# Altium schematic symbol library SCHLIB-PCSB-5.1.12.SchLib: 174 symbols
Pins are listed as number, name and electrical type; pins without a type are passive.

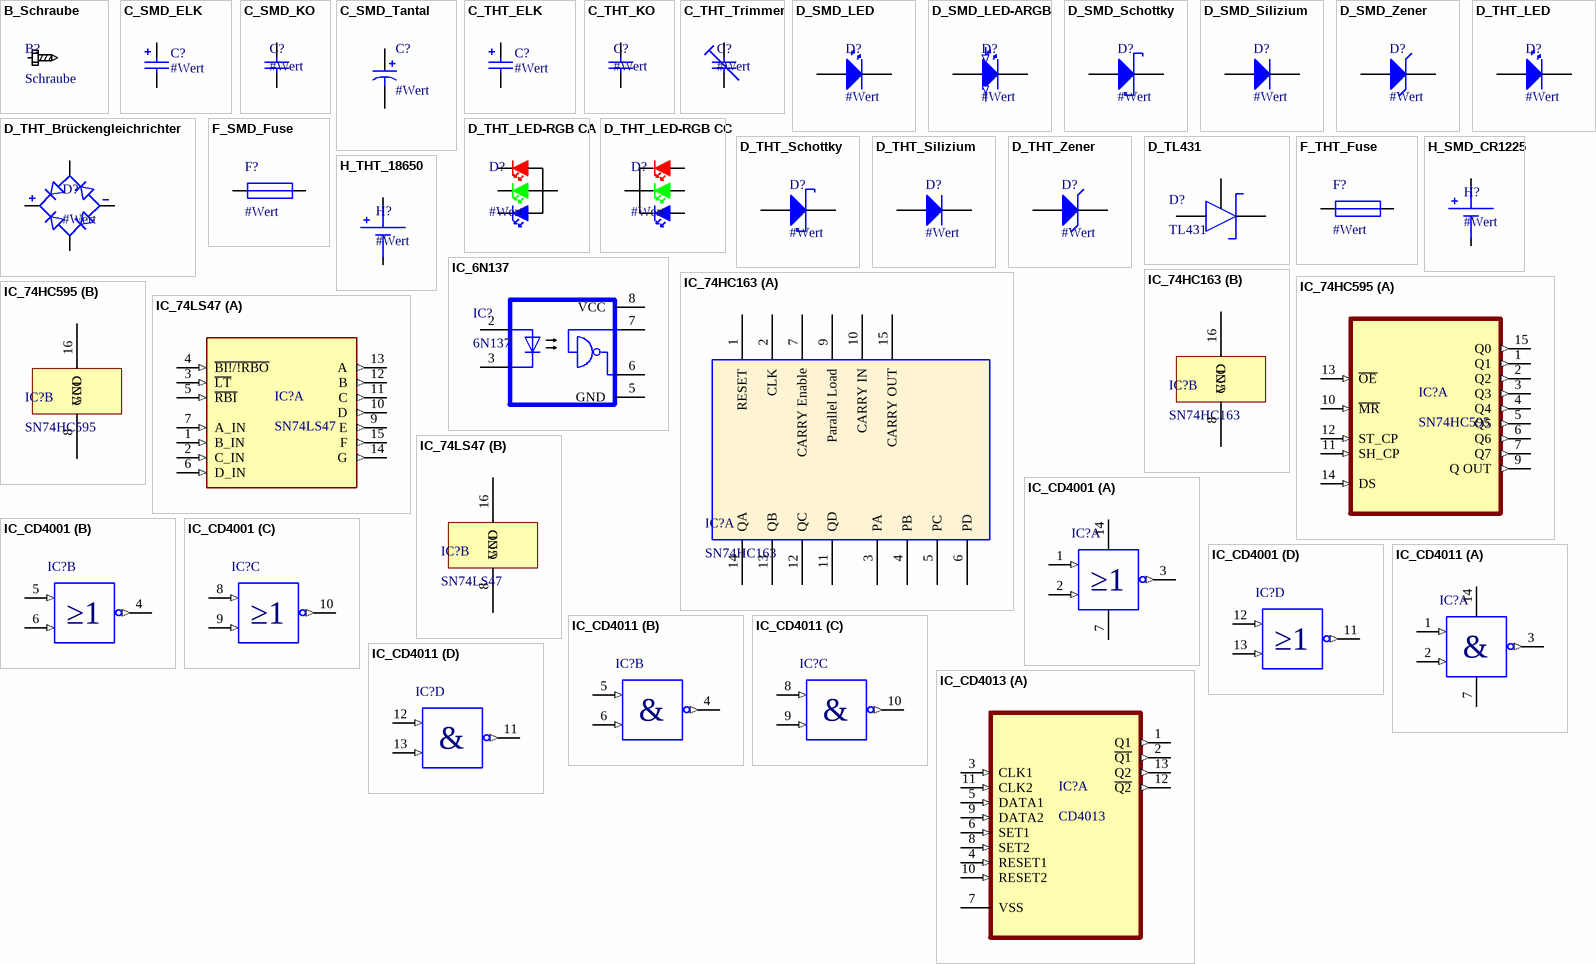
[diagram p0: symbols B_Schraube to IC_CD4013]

## B_Schraube
designator B?, comment Schraube
Schraubenloch für M3 Schrauben
footprint B_Schraube-M3 PAD (LB-2024-04-18)
footprint B_Schraube-M3 (LB-2024-04-18)
pins: 1 PAD

## C_SMD_ELK
designator C?, comment #Wert
SMD Elektrolytkondensator
footprint C_SMD_B-Typ (LB-2024-04-16)
footprint C_SMD_C-TYP (LB-2024-04-15)
footprint C_SMD_D-TYP (LB-2024-04-16)
footprint C_SMD_D8-TYP (LB-2024-04-16)
footprint C_SMD_F-TYP (LB-2024-04-16)
footprint C_SMD_G-TYP (LB-2024-04-16)
pins: 1, 2

## C_SMD_KO
designator C?, comment #Wert
Kondensator SMD Universal, Keramik, Folie, usw.
footprint C_SMD_0603 (LB-2024-04-17)
footprint C_SMD_0805 (LB-2024-04-17)
footprint C_SMD_1206 (LB-2024-04-17)
footprint C_SMD_1808C (LB-2024-04-17)
footprint C_SMD_2010R (LB-2024-04-17)
pins: 1, 2

## C_SMD_Tantal
designator C?, comment #Wert
Tantalkondensator
footprint C_SMD_Tan_1206 (LB-2024-04-25)
footprint C_SMD_B-Typ (LB-2024-04-16)
footprint C_SMD_C-TYP (LB-2024-04-15)
footprint C_SMD_D-TYP (LB-2024-04-16)
footprint C_SMD_D8-TYP (LB-2024-04-16)
footprint C_SMD_F-TYP (LB-2024-04-16)
footprint C_SMD_G-TYP (LB-2024-04-16)
pins: 1, 2

## C_THT_ELK
designator C?, comment #Wert
THT Elektrolytkondensator
footprint C_THT_RB-.3/.6 (LB-2024-04-15)
footprint C_THT_RB-.2/.4 (LB-2024-04-16)
footprint C_THT_RB-.1/.3 (LB-2024-04-15)
footprint C_THT_RB-.1/.2 (LB-2024-04-15)
pins: 1, 2

## C_THT_KO
designator C?, comment #Wert
Kondensator THT Universal, Keramik, Folie, usw.
footprint C_THT_RAD-0.2/.1 (LB-2024-04-17)
footprint C_THT_rad-7.2/2.5/5 (LB-2024-04-17)
footprint C_THT_RAD-7.2/3.5/5 (LB-2024-04-17)
footprint C_THT_RAD-.5/1.5
pins: 1, 2

## C_THT_Trimmer
designator C?, comment #Wert
Trimmkondensator
footprint C_THT_Trimmer (LB-2024-04-19)
pins: 1, 2

## D_SMD_LED
designator D?, comment #Wert
Diode SMD LED; Spannung For.: 1,8V-3,6V
footprint D_SMD_0603 (LB-2024-04-17)
footprint D_SMD_0805 (LB-2024-04-17)
footprint D_SMD_1206 (LB-2024-04-17)
footprint D_SMD_1808C (LB-2024-04-17)
footprint D_SMD_2010R (LB-2024-04-17)
pins: 1 A, 2 K

## D_SMD_LED-ARGB
designator D?, comment #Wert
Diode SMD ARGB
footprint D_SMD_LED-ARGB
pins: 1 K, 2 DIN (in), 3 A, 4 DOUT (out)

## D_SMD_Schottky
designator D?, comment #Wert
Diode SMD Schottky; Spannung Rev.: 0,4V
footprint D_SMD_0603 (LB-2024-04-17)
footprint D_SMD_0805 (LB-2024-04-17)
footprint D_SMD_1206 (LB-2024-04-17)
footprint D_SMD_1808C (LB-2024-04-17)
footprint D_SMD_2010R (LB-2024-04-17)
footprint D_SMD_DIO-123 (LB-2024-04-25)
footprint DO-214 (LB-2024-09-01)
footprint SOD-80-2
pins: 1 A, 2 K

## D_SMD_Silizium
designator D?, comment #Wert
Diode SMD Silizium; Spannung For.: 0,7V
footprint D_SMD_0603 (LB-2024-04-17)
footprint D_SMD_0805 (LB-2024-04-17)
footprint D_SMD_1206 (LB-2024-04-17)
footprint D_SMD_1808C (LB-2024-04-17)
footprint D_SMD_2010R (LB-2024-04-17)
footprint DO-214 (LB-2024-09-01)
footprint SOD-80-2
pins: 1 A, 2 K

## D_SMD_Zener
designator D?, comment #Wert
Diode SMD Zener
footprint D_SMD_0603 (LB-2024-04-17)
footprint D_SMD_0805 (LB-2024-04-17)
footprint D_SMD_1206 (LB-2024-04-17)
footprint D_SMD_1808C (LB-2024-04-17)
footprint D_SMD_2010R (LB-2024-04-17)
footprint DO-214 (LB-2024-09-01)
footprint SOD-80-2
pins: 1 A, 2 K

## D_THT_Brückengleichrichter
designator D?, comment #Wert
Bruckengleichrichter
footprint D_THT_FBR-Gr. (LB-2024-04-18)
footprint D_THT_FBR-Kl. (LB-2024-04-18)
footprint D_THT_FBR-R (LB-2024-11-20)
pins: 1 POS, 2 AC1, 3 AC2, 4 NEG

## D_THT_LED
designator D?, comment #Wert
Diode THT LED; Spannung For.: 1,8V-3,6V
footprint D_THT_LED-3 (LB-2024-04-17)
footprint D_THT_LED-5 (LB-2024-04-17)
pins: 1 A, 2 K

## D_THT_LED-RGB CA
designator D?, comment #Wert
RGB LED Common Anode
footprint D_THT_RGBLED
pins: 1, 2, 3, 4

## D_THT_LED-RGB CC
designator D?, comment #Wert
RGB LED Common Cathode
footprint D_THT_RGBLED
pins: 1, 2, 3, 4

## D_THT_Schottky
designator D?, comment #Wert
Diode THT Schottky; Spannung For.: 0,4V
footprint D_THT_0.4 (LB-2024-04-17)
footprint D_THT_0.5 (LB-2024-04-17)
footprint D_THT_0.6 (LB-2024-04-17)
pins: 1 A, 2 K

## D_THT_Silizium
designator D?, comment #Wert
Diode THT Silizium; Spannung For.: 0,7V
footprint D_THT_0.4 (LB-2024-04-17)
footprint D_THT_0.5 (LB-2024-04-17)
footprint D_THT_0.6 (LB-2024-04-17)
pins: 1 A, 2 K

## D_THT_Zener
designator D?, comment #Wert
Diode THT Zener
footprint D_THT_0.4 (LB-2024-04-17)
footprint D_THT_0.5 (LB-2024-04-17)
footprint D_THT_0.6 (LB-2024-04-17)
pins: 1 A, 2 K

## D_TL431
designator D?, comment TL431
Programmable Shunt Regulator Diode (NUR OHNE MFDT ENDE)
footprint D_THT_TO-92/3 (LB-2024-04-19)
footprint SOT-23
pins: 1 Kathode, 2 REF, 3 Anode

## F_SMD_Fuse
designator F?, comment #Wert
Sicherung
footprint F_SMD_0805 (LB-2024-04-17)
footprint F_SMD_0603 (LB-2024-04-17)
footprint F_SMD_Reel (LB-2024-09-01)
pins: 1, 2

## F_THT_Fuse
designator F?, comment #Wert
Sicherung
footprint F_THT_Fuse2pol (LB-2024-04-17)
footprint F_THT_bel-Fuse
pins: 1, 2

## H_SMD_CR1225
designator H?, comment #Wert
Batteriehalter CR1220/CR1225
footprint H_SMD_SMTM1225 (LB-2025-06-22)
pins: 1 +, 2 -

## H_THT_18650
designator H?, comment #Wert
Zellenzahlter
footprint W_THT_Batholder_18650 (LB-2024-04-25)
pins: 1 +, 2 -

## IC_6N137
designator IC?, comment 6N137
Optokoppler
footprint DIP-8 (LB-2024-04-17)
pins: 2 LED+, 3 LED-, 5 GND, 6 VO, 7 VE, 8 VCC

## IC_74HC163
designator IC?, comment SN74HC163
Counter-IC; Spannung: 2-6V
footprint DIP-16 (LB-2024-04-17)
part A pins: 1 RESET, 2 CLK, 3 PA, 4 PB, 5 PC, 6 PD, 7 CARRY Enable, 9 Parallel Load, 10 CARRY IN, 11 QD, 12 QC, 13 QB, 14 QA, 15 CARRY OUT
part B pins: 8 GND, 16 VCC

## IC_74HC595
designator IC?, comment SN74HC595
Schieberegister; MP: 74HC595PW/AUJ; MF: NXP Semiconductors
footprint DIP-16 (LB-2024-04-17)
footprint SO-16 (LB-2024-04-17)
footprint SOP-16
part A pins: 1 Q1 (out), 2 Q2 (out), 3 Q3 (out), 4 Q4 (out), 5 Q5 (out), 6 Q6 (out), 7 Q7 (out), 9 Q OUT (out), 10 ~{MR} (in), 11 SH_CP (in), 12 ST_CP (in), 13 ~{OE} (in), 14 DS (in), 15 Q0 (out)
part B pins: 8 GND, 16 VCC

## IC_74LS47
designator IC?, comment SN74LS47
BCD-to-Seven-Segment Decoders/Drivers 16-PDIP 0 to 70; MP: SN74LS47N; MF: Texas Instruments
footprint DIP-16 (LB-2024-04-17)
footprint SO-16 (LB-2024-04-17)
part A pins: 1 B_IN (in), 2 C_IN (in), 3 ~{LT} (in), 4 ~{BI!/!RBO} (in), 5 ~{RBI} (in), 6 D_IN (in), 7 A_IN (in), 9 E (out), 10 D (out), 11 C (out), 12 B (out), 13 A (out), 14 G (out), 15 F (out)
part B pins: 8 GND, 16 VCC

## IC_CD4001
designator IC?, comment CD4001  (value not drawn)
NOR Gatter
footprint DIP-14 (LB-2024-04-17)
footprint SO-14 (LB-2024-04-17)
part A pins: 1 A (in), 2 B (in), 3 OUTAB (out), 7 GND (power), 14 V+ (power)
part B pins: 4 OUTCD (out), 5 C (in), 6 D (in)
part C pins: 8 E (in), 9 F (in), 10 OUTEF (out)
part D pins: 11 OUTGH (out), 12 G (in), 13 H (in)

## IC_CD4011
designator IC?, comment CD4011  (value not drawn)
NAND Gatter
footprint DIP-14 (LB-2024-04-17)
footprint SO-14 (LB-2024-04-17)
part A pins: 1 A (in), 2 B (in), 3 OUTAB (out), 7 GND (power), 14 V+ (power)
part B pins: 4 OUTCD (out), 5 C (in), 6 D (in)
part C pins: 8 E (in), 9 F (in), 10 OUTEF (out)
part D pins: 11 OUTGH (out), 12 G (in), 13 H (in)

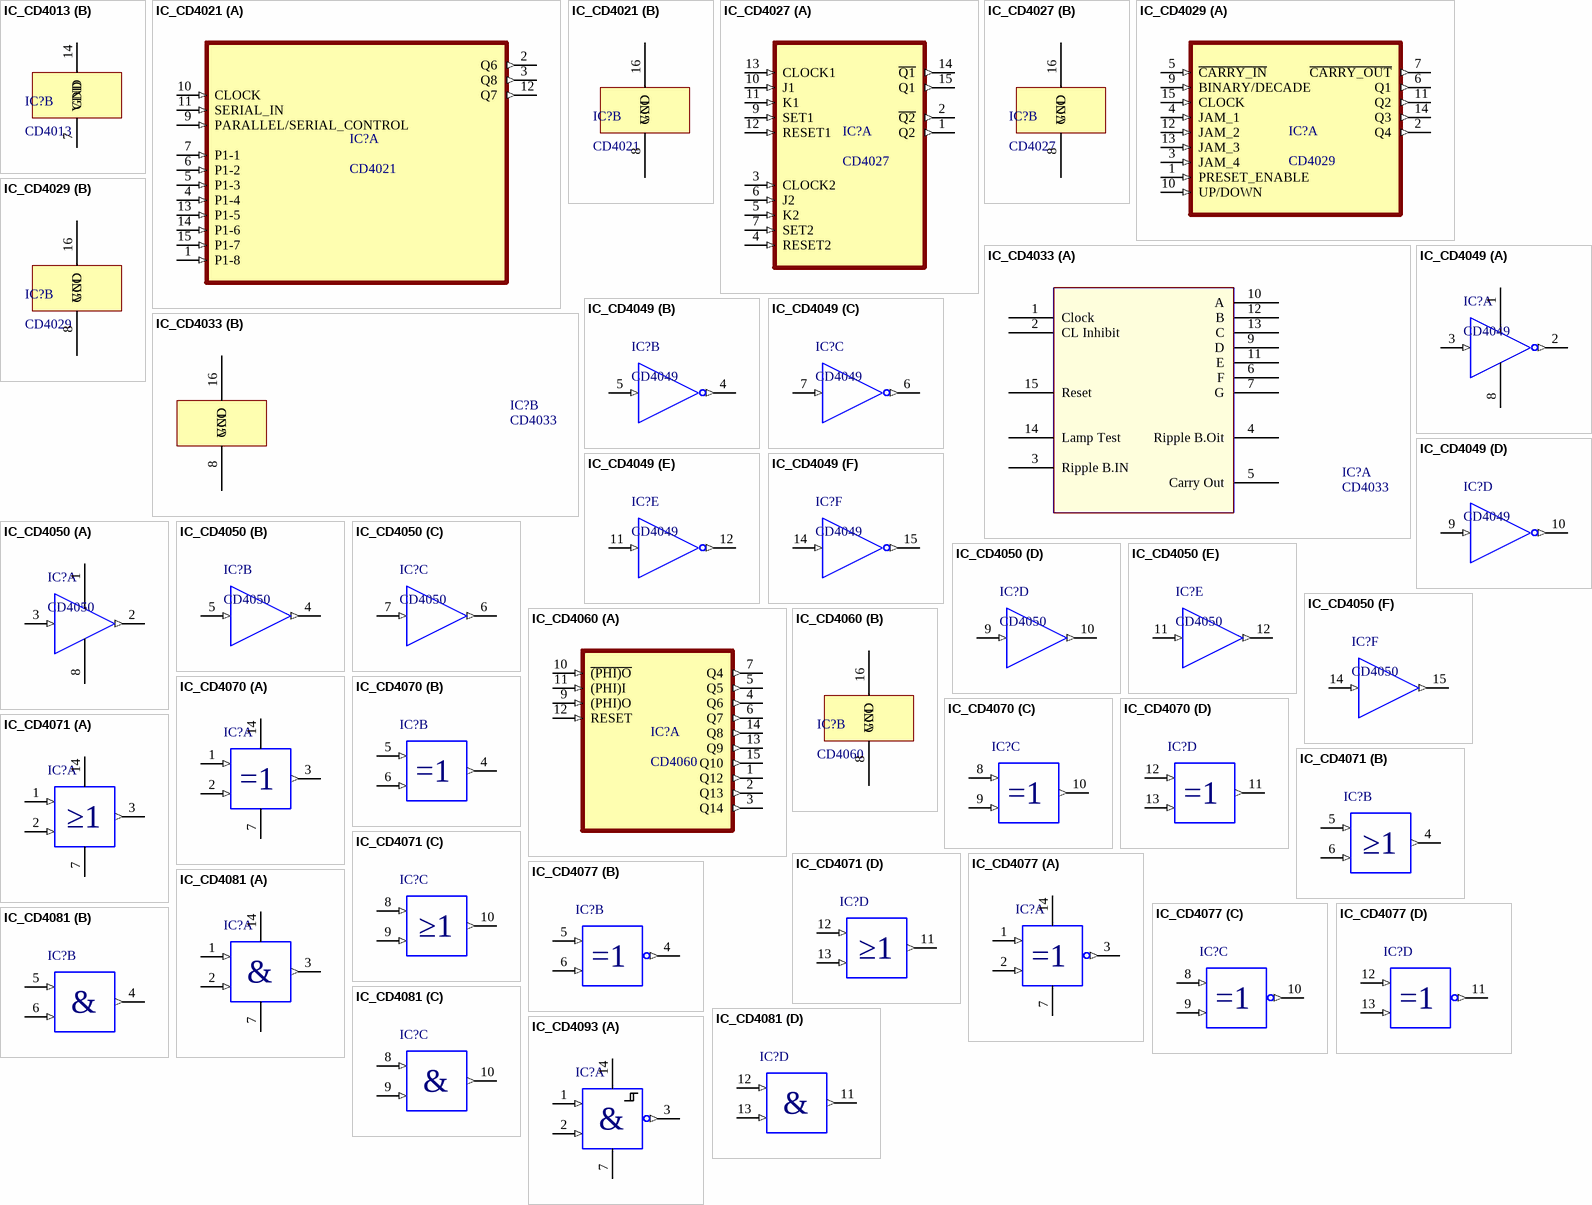
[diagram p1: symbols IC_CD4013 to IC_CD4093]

## IC_CD4013
designator IC?, comment CD4013
D-FlipFlop
footprint SO-14 (LB-2024-04-17)
footprint DIP-14 (LB-2024-04-17)
part A pins: 1 Q1 (out), 2 ~{Q1} (out), 3 CLK1 (in), 4 RESET1 (in), 5 DATA1 (in), 6 SET1 (in), 7 VSS (power), 8 SET2 (in), 9 DATA2 (in), 10 RESET2 (in), 11 CLK2 (in), 12 ~{Q2} (out), 13 Q2 (out)
part B pins: 7 GND, 14 VDD (power)

## IC_CD4021
designator IC?, comment CD4021
Schieberegister
footprint DIP-16 (LB-2024-04-17)
footprint SO-16 (LB-2024-04-17)
part A pins: 1 P1-8 (in), 2 Q6 (out), 3 Q8 (out), 4 P1-4 (in), 5 P1-3 (in), 6 P1-2 (in), 7 P1-1 (in), 9 PARALLEL/SERIAL_CONTROL (in), 10 CLOCK (in), 11 SERIAL_IN (in), 12 Q7 (out), 13 P1-5 (in), 14 P1-6 (in), 15 P1-7 (in)
part B pins: 8 GND, 16 VCC

## IC_CD4027
designator IC?, comment CD4027
JK-FlipFlop
footprint DIP-16 (LB-2024-04-17)
footprint SO-16 (LB-2024-04-17)
part A pins: 1 Q2 (out), 2 ~{Q2} (out), 3 CLOCK2 (in), 4 RESET2 (in), 5 K2 (in), 6 J2 (in), 7 SET2 (in), 9 SET1 (in), 10 J1 (in), 11 K1 (in), 12 RESET1 (in), 13 CLOCK1 (in), 14 ~{Q1} (out), 15 Q1 (out)
part B pins: 8 GND, 16 VCC

## IC_CD4029
designator IC?, comment CD4029
UP/Down Counter
footprint DIP-16 (LB-2024-04-17)
footprint SO-16 (LB-2024-04-17)
part A pins: 1 PRESET_ENABLE (in), 2 Q4 (out), 3 JAM_4 (in), 4 JAM_1 (in), 5 ~{CARRY_IN} (in), 6 Q1 (out), 7 ~{CARRY_OUT} (out), 9 BINARY/DECADE (in), 10 UP/DOWN (in), 11 Q2 (out), 12 JAM_2 (in), 13 JAM_3 (in), 14 Q3 (out), 15 CLOCK (in)
part B pins: 8 GND, 16 VCC

## IC_CD4033
designator IC?, comment CD4033
Counter/Divider
footprint DIP-16 (LB-2024-04-17)
footprint SO-16 (LB-2024-04-17)
part A pins: 1 Clock, 2 CL Inhibit, 3 Ripple B.IN, 4 Ripple B.Oit, 5 Carry Out, 6 F, 7 G, 9 D, 10 A, 11 E, 12 B, 13 C, 14 Lamp Test, 15 Reset
part B pins: 8 GND, 16 VCC

## IC_CD4049
designator IC?, comment CD4049
Hex Inverter
footprint DIP-16 (LB-2024-04-17)
part A pins: 1 V+ (power), 2 OUTAB (out), 3 B (in), 8 GND (power)
part B pins: 4 OUTAB (out), 5 B (in)
part C pins: 6 OUTAB (out), 7 B (in)
part D pins: 9 B (in), 10 OUTAB (out)
part E pins: 11 B (in), 12 OUTAB (out)
part F pins: 14 B (in), 15 OUTAB (out)

## IC_CD4050
designator IC?, comment CD4050
Hex Buffer
footprint DIP-16 (LB-2024-04-17)
part A pins: 1 V+ (power), 2 OUTAB (out), 3 B (in), 8 GND (power)
part B pins: 4 OUTAB (out), 5 B (in)
part C pins: 6 OUTAB (out), 7 B (in)
part D pins: 9 B (in), 10 OUTAB (out)
part E pins: 11 B (in), 12 OUTAB (out)
part F pins: 14 B (in), 15 OUTAB (out)

## IC_CD4060
designator IC?, comment CD4060
14 Stage Counter
footprint DIP-16 (LB-2024-04-17)
footprint SO-16 (LB-2024-04-17)
part A pins: 1 Q12 (out), 2 Q13 (out), 3 Q14 (out), 4 Q6 (out), 5 Q5 (out), 6 Q7 (out), 7 Q4 (out), 9 (PHI)O (in), 10 ~{(PHI)O} (in), 11 (PHI)I (in), 12 RESET (in), 13 Q9 (out), 14 Q8 (out), 15 Q10 (out)
part B pins: 8 GND, 16 VCC

## IC_CD4070
designator IC?, comment CD4070  (value not drawn)
XOR Gatter
footprint DIP-14 (LB-2024-04-17)
footprint SO-14 (LB-2024-04-17)
part A pins: 1 A (in), 2 B (in), 3 OUTAB (out), 7 GND (power), 14 V+ (power)
part B pins: 4 OUTCD (out), 5 C (in), 6 D (in)
part C pins: 8 E (in), 9 F (in), 10 OUTEF (out)
part D pins: 11 OUTGH (out), 12 G (in), 13 H (in)

## IC_CD4071
designator IC?, comment CD4071  (value not drawn)
OR Gatter
footprint DIP-14 (LB-2024-04-17)
footprint SO-14 (LB-2024-04-17)
part A pins: 1 A (in), 2 B (in), 3 OUTAB (out), 7 GND (power), 14 V+ (power)
part B pins: 4 OUTCD (out), 5 C (in), 6 D (in)
part C pins: 8 E (in), 9 F (in), 10 OUTEF (out)
part D pins: 11 OUTGH (out), 12 G (in), 13 H (in)

## IC_CD4077
designator IC?, comment CD4077  (value not drawn)
XNOR Gatter
footprint DIP-14 (LB-2024-04-17)
footprint SO-14 (LB-2024-04-17)
part A pins: 1 A (in), 2 B (in), 3 OUTAB (out), 7 GND (power), 14 V+ (power)
part B pins: 4 OUTCD (out), 5 C (in), 6 D (in)
part C pins: 8 E (in), 9 F (in), 10 OUTEF (out)
part D pins: 11 OUTGH (out), 12 G (in), 13 H (in)

## IC_CD4081
designator IC?, comment CD4081  (value not drawn)
AND Gatter
footprint DIP-14 (LB-2024-04-17)
footprint SO-14 (LB-2024-04-17)
part A pins: 1 A (in), 2 B (in), 3 OUTAB (out), 7 GND (power), 14 V+ (power)
part B pins: 4 OUTCD (out), 5 C (in), 6 D (in)
part C pins: 8 E (in), 9 F (in), 10 OUTEF (out)
part D pins: 11 OUTGH (out), 12 G (in), 13 H (in)

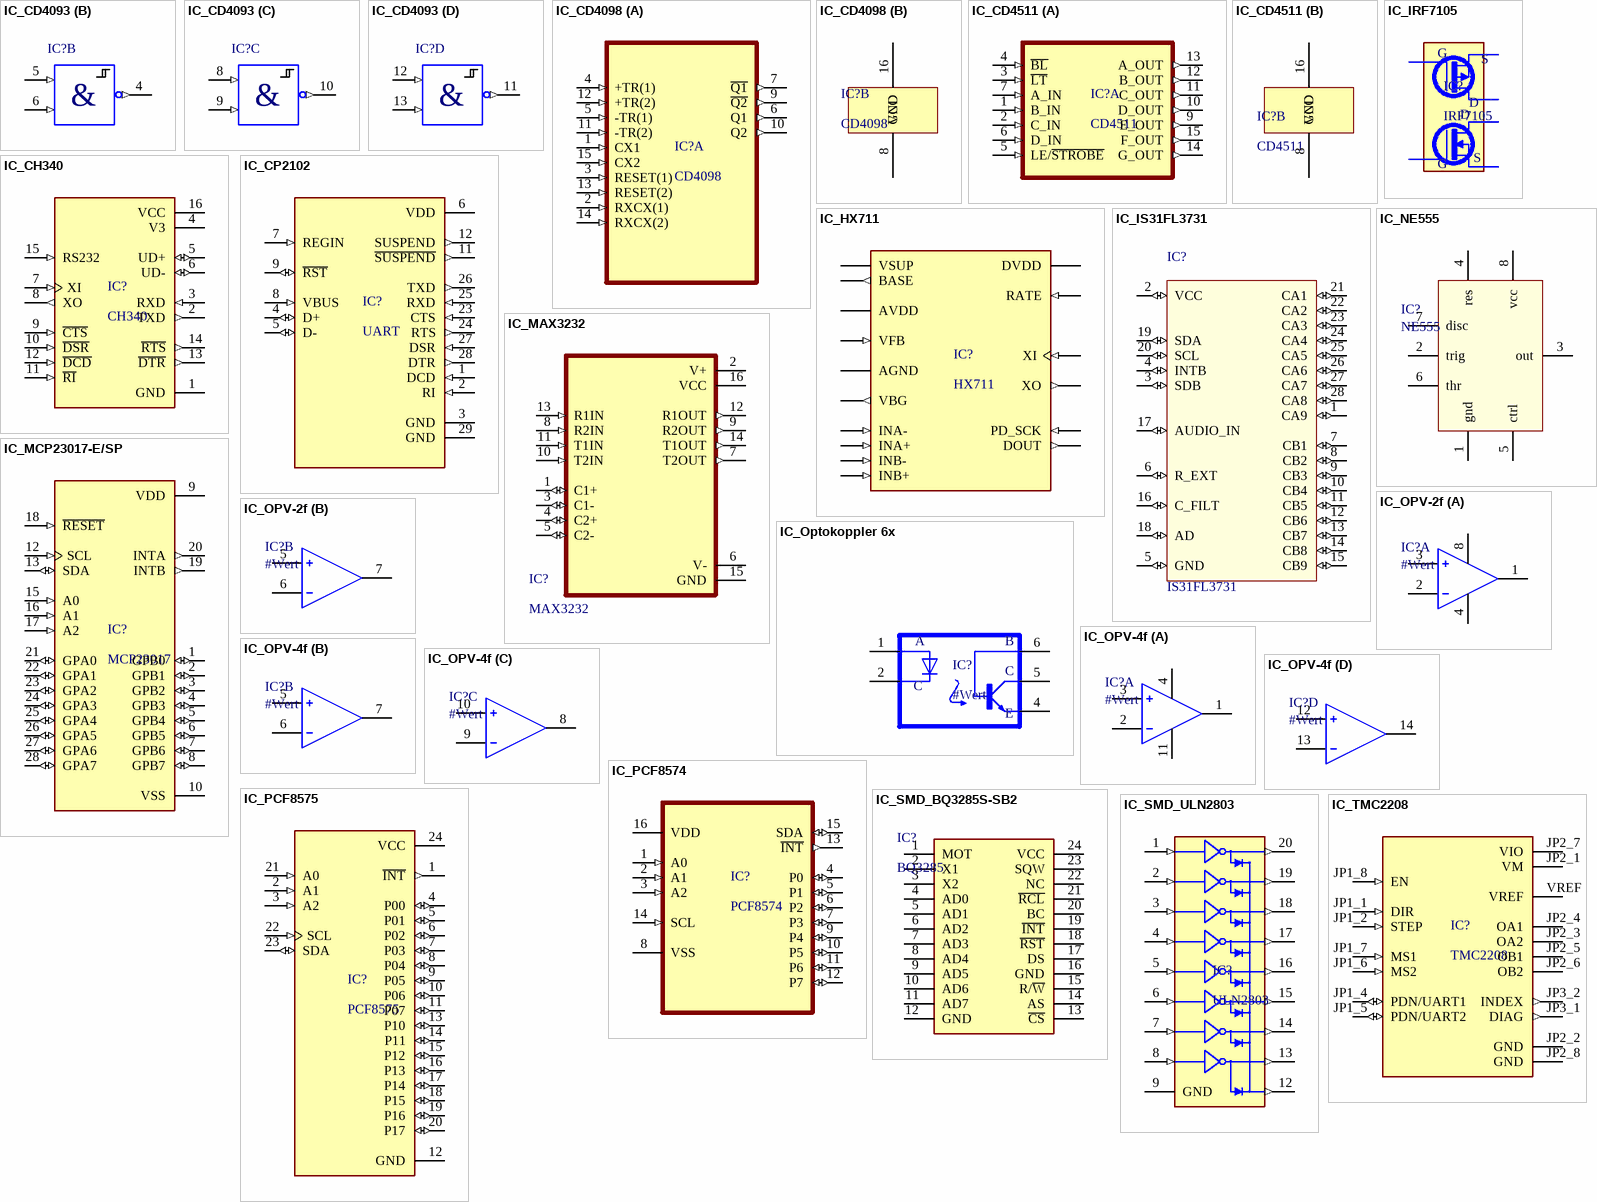
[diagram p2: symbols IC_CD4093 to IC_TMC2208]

## IC_CD4093
designator IC?, comment CD4093  (value not drawn)
Schmitttrigger NAND Gatter
footprint DIP-14 (LB-2024-04-17)
footprint SO-14 (LB-2024-04-17)
part A pins: 1 A (in), 2 B (in), 3 OUTAB (out), 7 GND (power), 14 V+ (power)
part B pins: 4 OUTCD (out), 5 C (in), 6 D (in)
part C pins: 8 E (in), 9 F (in), 10 OUTEF (out)
part D pins: 11 OUTGH (out), 12 G (in), 13 H (in)

## IC_CD4098
designator IC?, comment CD4098
Dual Monostable Multivibrator
footprint DIP-16 (LB-2024-04-17)
part A pins: 1 CX1 (in), 2 RXCX(1) (in), 3 RESET(1) (in), 4 +TR(1) (in), 5 -TR(1) (in), 6 Q1 (out), 7 ~{Q1} (out), 9 ~{Q2} (out), 10 Q2 (out), 11 -TR(2) (in), 12 +TR(2) (in), 13 RESET(2) (in), 14 RXCX(2) (in), 15 CX2 (in)
part B pins: 8 GND, 16 VCC

## IC_CD4511
designator IC?, comment CD4511
BCD
footprint DIP-16 (LB-2024-04-17)
part A pins: 1 B_IN (in), 2 C_IN (in), 3 ~{LT} (in), 4 ~{BL} (in), 5 LE/~{STROBE} (in), 6 D_IN (in), 7 A_IN (in), 9 E_OUT (out), 10 D_OUT (out), 11 C_OUT (out), 12 B_OUT (out), 13 A_OUT (out), 14 G_OUT (out), 15 F_OUT (out)
part B pins: 8 GND, 16 VCC

## IC_CH340
designator IC?, comment CH340
UART
footprint SO-16 (LB-2024-04-17)
pins: 1 GND (power), 2 TXD (out), 3 RXD (in), 4 V3 (power), 5 UD+ (io), 6 UD- (io), 7 XI (in), 8 XO (out), 9 ~{CTS} (in), 10 ~{DSR} (in), 11 ~{RI} (in), 12 ~{DCD} (in), 13 ~{DTR} (out), 14 ~{RTS} (out), 15 RS232 (in), 16 VCC (power)

## IC_CP2102
designator IC?, comment UART
footprint QFN50-29N (LB-2024-09-01)
pins: 1 DCD (in), 2 RI (in), 3 GND (power), 4 D+ (io), 5 D- (io), 6 VDD (power), 7 REGIN (in), 8 VBUS (in), 9 ~{RST} (io), 11 ~{SUSPEND} (out), 12 SUSPEND (out), 23 CTS (in), 24 RTS (out), 25 RXD (in), 26 TXD (out), 27 DSR (in), 28 DTR (out), 29 GND (power)

## IC_HX711
designator IC?, comment HX711
Wägezelle ADC
footprint SO-16 (LB-2024-04-17)
pins: 1 VSUP (power), 2 BASE (out), 3 AVDD (power), 4 VFB (in), 5 AGND (power), 6 VBG (out), 7 INA- (in), 8 INA+ (in), 9 INB- (in), 10 INB+ (in), 11 PD_SCK (in), 12 DOUT (out), 13 XO (out), 14 XI (in), 15 RATE (in), 16 DVDD (power)

## IC_IRF7105
designator IC?, comment IRF7105
Mosfet Array
footprint SO-8 (LB-2024-04-17)
pins: 1 S, 2 G, 3 S1, 4 G1, 5 D1, 6 D1A (io), 7 D, 8 DA (io)

## IC_IS31FL3731
designator IC?, comment IS31FL3731
Charlieplexing
footprint QFN-28 (LB-2024-09-01)
footprint SSOP28 (LB-2024-09-01)
pins: 1 CA9 (io), 2 VCC (io), 3 SDB (io), 4 INTB (io), 5 GND (io), 6 R_EXT (io), 7 CB1 (io), 8 CB2 (io), 9 CB3 (io), 10 CB4 (io), 11 CB5 (io), 12 CB6 (io), 13 CB7 (io), 14 CB8 (io), 15 CB9 (io), 16 C_FILT (io), 17 AUDIO_IN (io), 18 AD (io), 19 SDA (io), 20 SCL (io), 21 CA1 (io), 22 CA2 (io), 23 CA3 (io), 24 CA4 (io), 25 CA5 (io), 26 CA6 (io), 27 CA7 (io), 28 CA8 (io)

## IC_MAX3232
designator IC?, comment MAX3232
RS-232 Line Driver
footprint SO-16 (LB-2024-04-17)
pins: 1 C1+ (io), 2 V+ (power), 3 C1- (io), 4 C2+ (io), 5 C2- (io), 6 V- (power), 7 T2OUT (out), 8 R2IN (in), 9 R2OUT (out), 10 T2IN (in), 11 T1IN (in), 12 R1OUT (out), 13 R1IN (in), 14 T1OUT (out), 15 GND (power), 16 VCC (power)

## IC_MCP23017-E/SP
designator IC?, comment MCP23017
I2C Port Expander
footprint DIP-28 (LB-2024-04-17)
pins: 1 GPB0 (io), 2 GPB1 (io), 3 GPB2 (io), 4 GPB3 (io), 5 GPB4 (io), 6 GPB5 (io), 7 GPB6 (io), 8 GPB7 (io), 9 VDD (power), 10 VSS (power), 12 SCL (in), 13 SDA (io), 15 A0 (in), 16 A1 (in), 17 A2 (in), 18 ~{RESET} (in), 19 INTB (out), 20 INTA (out), 21 GPA0 (io), 22 GPA1 (io), 23 GPA2 (io), 24 GPA3 (io), 25 GPA4 (io), 26 GPA5 (io), 27 GPA6 (io), 28 GPA7 (io)

## IC_NE555
designator IC?, comment NE555
Timer
footprint DIP-8 (LB-2024-04-17)
footprint SO-8 (LB-2024-04-17)
pins: 1 gnd, 2 trig, 3 out, 4 res, 5 ctrl, 6 thr, 7 disc, 8 vcc

## IC_Optokoppler 6x
designator IC?, comment #Wert
Optokoppler like CNY17
footprint DIP-6 (LB-2024-04-17)
pins: 1 A, 2 C, 4 E, 5 C`, 6

## IC_OPV-2f
designator IC?, comment #Wert
Operationsverstärker
footprint DIP-8 (LB-2024-04-17)
footprint SO-8 (LB-2024-04-17)
part A pins: 1 out, 2 I, 3 NI, 4 Vee, 8 Vcc
part B pins: 5 NI, 6 I, 7 out

## IC_OPV-4f
designator IC?, comment #Wert
Operationsverstärker
footprint DIP-14 (LB-2024-04-17)
footprint SO-14 (LB-2024-04-17)
part A pins: 1 out, 2 I, 3 NI, 4 Vcc, 11 Vee
part B pins: 5 NI, 6 I, 7 out
part C pins: 8 out, 9 I, 10 NI
part D pins: 12 NI, 13 I, 14 out

## IC_PCF8574
designator IC?, comment PCF8574
I/O Expander
footprint SOIC-16 (LB-2025-02-02)
pins: 1 A0 (in), 2 A1 (in), 3 A2 (in), 4 P0 (io), 5 P1 (io), 6 P2 (io), 7 P3 (io), 8 VSS, 9 P4 (io), 10 P5 (io), 11 P6 (io), 12 P7 (io), 13 ~{INT} (out), 14 SCL (in), 15 SDA (io), 16 VDD (power)

## IC_PCF8575
designator IC?, comment PCF8575
I/O Expander
footprint SOIC-24
pins: 1 ~{INT} (out), 2 A1 (in), 3 A2 (in), 4 P00 (io), 5 P01 (io), 6 P02 (io), 7 P03 (io), 8 P04 (io), 9 P05 (io), 10 P06 (io), 11 P07 (io), 12 GND (power), 13 P10 (io), 14 P11 (io), 15 P12 (io), 16 P13 (io), 17 P14 (io), 18 P15 (io), 19 P16 (io), 20 P17 (io), 21 A0 (in), 22 SCL (in), 23 SDA (io), 24 VCC (power)

## IC_SMD_BQ3285S-SB2
designator IC?, comment BQ3285
RTC-Chip
footprint SOIC-24
pins: 1 MOT, 2 X1, 3 X2, 4 AD0, 5 AD1, 6 AD2, 7 AD3, 8 AD4, 9 AD5, 10 AD6, 11 AD7, 12 GND, 13 ~{CS}, 14 AS, 15 R/~{W}, 16 GND, 17 DS, 18 ~{RST}, 19 ~{INT}, 20 BC, 21 ~{RCL}, 22 NC, 23 SQW, 24 VCC

## IC_SMD_ULN2803
designator IC?, comment ULN2803
Darlington-Transistor
footprint SOIC-20 (LB-2025-01-10)
pins: 1 IN_1 (in), 2 IN_2 (in), 3 IN_3 (in), 4 IN_4 (in), 5 IN_5 (in), 6 IN_6 (in), 7 IN_7 (in), 8 IN_8 (in), 9 GND (power), 12 COMMON (out), 13 OUT_8 (out), 14 OUT_7 (out), 15 OUT_6 (out), 16 OUT_5 (out), 17 OUT_4 (out), 18 OUT_3 (out), 19 OUT_2 (out), 20 OUT_1 (out)

## IC_TMC2208
designator IC?, comment TMC2208
Schrittmotortreiber
footprint IC_TMC2208 (LB-24-10-23)
pins: JP1_1 DIR (in), JP1_2 STEP (in), JP1_4 PDN/UART1 (io), JP1_5 PDN/UART2 (io), JP1_6 MS2 (in), JP1_7 MS1 (in), JP1_8 EN (in), JP2_1 VM (power), JP2_2 GND (power), JP2_3 OA2, JP2_4 OA1, JP2_5 OB1, JP2_6 OB2, JP2_7 VIO (power), JP2_8 GND (power), JP3_1 DIAG (out), JP3_2 INDEX (out), VREF

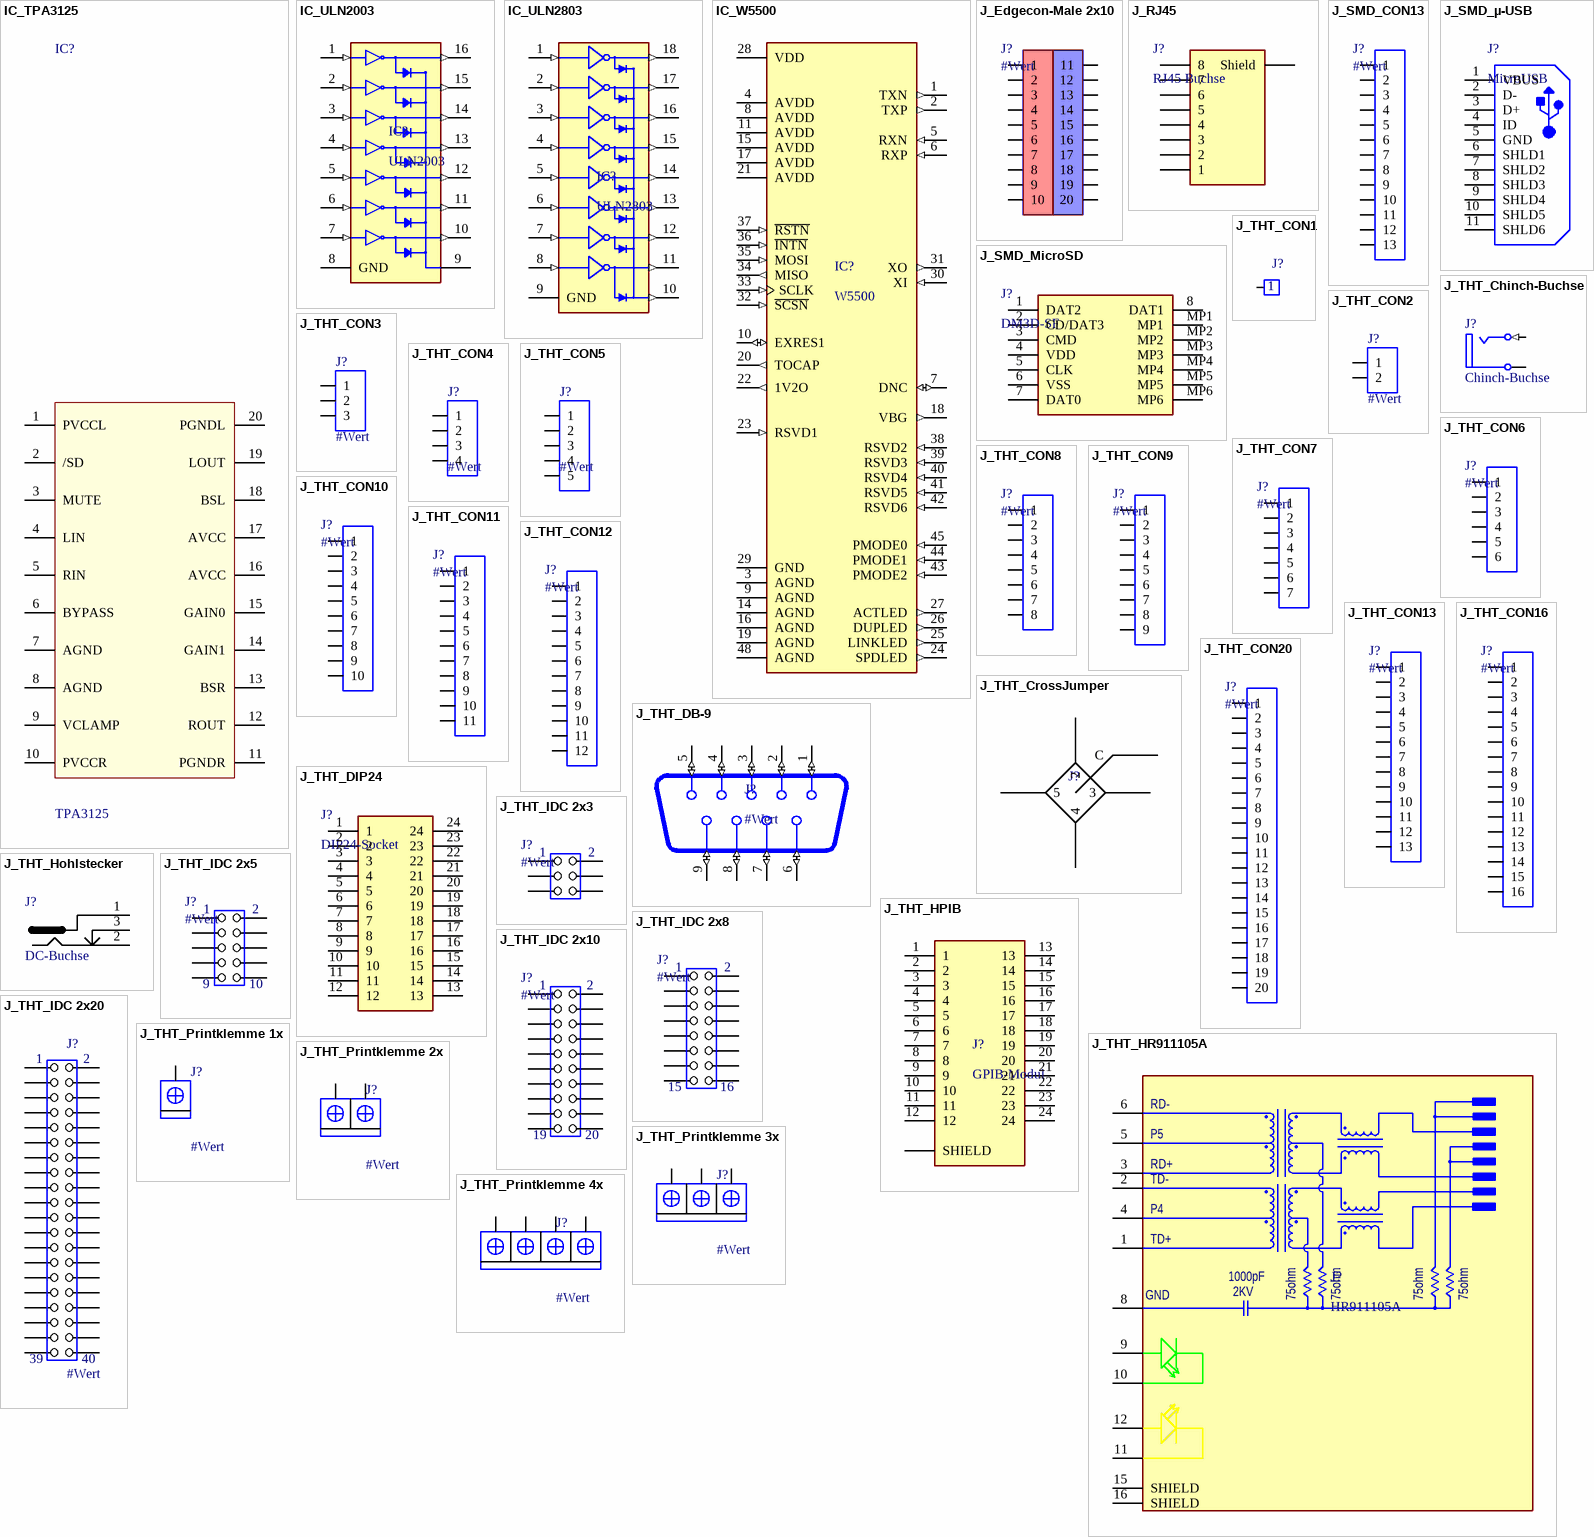
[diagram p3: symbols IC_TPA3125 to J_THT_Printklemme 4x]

## IC_TPA3125
designator IC?, comment TPA3125
Class-D IC
footprint DIP-20 (LB-2024-04-17)
pins: 1 PVCCL, 2 /SD, 3 MUTE, 4 LIN, 5 RIN, 6 BYPASS, 7 AGND, 8 AGND, 9 VCLAMP, 10 PVCCR, 11 PGNDR, 12 ROUT, 13 BSR, 14 GAIN1, 15 GAIN0, 16 AVCC, 17 AVCC, 18 BSL, 19 LOUT, 20 PGNDL

## IC_ULN2003
designator IC?, comment ULN2003
Darlingtor-Transistor
footprint DIP-16 (LB-2024-04-17)
footprint SO-16 (LB-2024-04-17)
pins: 1 1B (in), 2 2B (in), 3 3B (in), 4 4B (in), 5 5B (in), 6 6B (in), 7 7B (in), 8 GND (power), 9 COM, 10 7C (out), 11 6C (out), 12 5C (out), 13 4C (out), 14 3C (out), 15 2C (out), 16 1C (out)

## IC_ULN2803
designator IC?, comment ULN2803
Darlington-Transistor
footprint DIP-18 (LB-2024-04-17)
pins: 1 IN_1 (in), 2 IN_2 (in), 3 IN_3 (in), 4 IN_4 (in), 5 IN_5 (in), 6 IN_6 (in), 7 IN_7 (in), 8 IN_8 (in), 9 GND (power), 10 COMMON (out), 11 OUT_8 (out), 12 OUT_7 (out), 13 OUT_6 (out), 14 OUT_5 (out), 15 OUT_4 (out), 16 OUT_3 (out), 17 OUT_2 (out), 18 OUT_1 (out)

## IC_W5500
designator IC?, comment W5500
Ethernet Controller
footprint QFP50P900X900X160-48N
pins: 1 TXN (out), 2 TXP (out), 3 AGND (power), 4 AVDD (power), 5 RXN (in), 6 RXP (in), 7 DNC (io), 8 AVDD (power), 9 AGND (power), 10 EXRES1 (io), 11 AVDD (power), 14 AGND (power), 15 AVDD (power), 16 AGND (power), 17 AVDD (power), 18 VBG (out), 19 AGND (power), 20 TOCAP (out), 21 AVDD (power), 22 1V2O (out), 23 RSVD1 (in), 24 SPDLED (out), 25 LINKLED (out), 26 DUPLED (out), 27 ACTLED (out), 28 VDD (power), 29 GND, 30 XI (in), 31 XO (out), 32 ~{SCSN} (in), 33 SCLK (in), 34 MISO (out), 35 MOSI (in), 36 ~{INTN} (in), 37 ~{RSTN} (in), 38 RSVD2 (in), 39 RSVD3 (in), 40 RSVD4 (in), 41 RSVD5 (in), 42 RSVD6 (in), 43 PMODE2 (in), 44 PMODE1 (in), 45 PMODE0 (in), 48 AGND (power)

## J_Edgecon-Male 2x10
designator J?, comment #Wert
Stecker
footprint J_Edgecon-Male_2x10 (PS-2024-06-15)
pins: 1, 2, 3, 4, 5, 6, 7, 8, 9, 10, 11, 12, 13, 14, 15, 16, 17, 18, 19, 20

## J_RJ45
designator J?, comment RJ45 Buchse
Connector
footprint J_SMD_RJ45 (LB-2024-05-31)
footprint J_TE-RJ45-8L-B (LB-2024-11-29)
pins: 1, 2, 3, 4, 5, 6, 7, 8, MP Shield

## J_SMD_CON13
designator J?, comment #Wert
Stecker
footprint SIP-13-SMD (LB-2024-04-17)
pins: 1, 2, 3, 4, 5, 6, 7, 8, 9, 10, 11, 12, 13

## J_SMD_MicroSD
designator J?, comment DM3D-SF
MicroSD-Holder
footprint J_SMD_DM3DSF (LB-2025-02-19)
pins: 1 DAT2, 2 CD/DAT3, 3 CMD, 4 VDD, 5 CLK, 6 VSS, 7 DAT0, 8 DAT1, MP1, MP2, MP3, MP4, MP5, MP6

## J_SMD_µ-USB
designator J?, comment MicroUSB
Micro USB Buchse
footprint J-SMD-Micro-USB (LB-2024-04-18)
pins: 1 VBUS, 2 D-, 3 D+, 4 ID, 5 GND, 6 SHLD1, 7 SHLD2, 8 SHLD3, 9 SHLD4, 10 SHLD5, 11 SHLD6

## J_THT_Chinch-Buchse
designator J?, comment Chinch-Buchse
footprint J_THT_CHINCH (LB-2024-04-19)
pins: 1 T (in) "Tip", 2 S (power) "Sleeve (Ground)"

## J_THT_CON1
designator J?, comment #Wert  (value not drawn)
Stecker
footprint SIP-1 (LB-2024-04-17)
pins: 1

## J_THT_CON2
designator J?, comment #Wert
Stecker
footprint SIP-2 (LB-2024-04-17)
pins: 1, 2

## J_THT_CON3
designator J?, comment #Wert
Stecker
footprint Sip-3 (LB-2024-04-17)
footprint Sip-3-V (LB-2024-04-17)
pins: 1, 2, 3

## J_THT_CON4
designator J?, comment #Wert
Stecker
footprint Sip-4 (LB-2024-04-17)
footprint Sip-4-V (LB-2024-04-17)
pins: 1, 2, 3, 4

## J_THT_CON5
designator J?, comment #Wert
Stecker
footprint SIP-5 (LB-2024-04-17)
pins: 1, 2, 3, 4, 5

## J_THT_CON6
designator J?, comment #Wert
Stecker
footprint SIP-6 (LB-2024-04-17)
pins: 1, 2, 3, 4, 5, 6

## J_THT_CON7
designator J?, comment #Wert
Stecker
footprint SIP-7 (LB-2024-04-17)
pins: 1, 2, 3, 4, 5, 6, 7

## J_THT_CON8
designator J?, comment #Wert
Stecker
footprint SIP-8 (LB-2024-04-17)
pins: 1, 2, 3, 4, 5, 6, 7, 8

## J_THT_CON9
designator J?, comment #Wert
Stecker
footprint SIP-9 (LB-2024-04-17)
pins: 1, 2, 3, 4, 5, 6, 7, 8, 9

## J_THT_CON10
designator J?, comment #Wert
Stecker
footprint SIP-10 (LB-2024-04-17)
pins: 1, 2, 3, 4, 5, 6, 7, 8, 9, 10

## J_THT_CON11
designator J?, comment #Wert
Stecker
footprint SIP-11 (LB-2024-04-17)
pins: 1, 2, 3, 4, 5, 6, 7, 8, 9, 10, 11

## J_THT_CON12
designator J?, comment #Wert
Stecker
footprint SIP-12 (LB-2024-04-17)
pins: 1, 2, 3, 4, 5, 6, 7, 8, 9, 10, 11, 12

## J_THT_CON13
designator J?, comment #Wert
Stecker
footprint SIP-13 (LB-2024-04-17)
pins: 1, 2, 3, 4, 5, 6, 7, 8, 9, 10, 11, 12, 13

## J_THT_CON16
designator J?, comment #Wert
Stecker
footprint SIP-16 (LB-2024-04-17)
pins: 1, 2, 3, 4, 5, 6, 7, 8, 9, 10, 11, 12, 13, 14, 15, 16

## J_THT_CON20
designator J?, comment #Wert
Stecker
footprint SIP-20 (LB-2024-04-17)
pins: 1, 2, 3, 4, 5, 6, 7, 8, 9, 10, 11, 12, 13, 14, 15, 16, 17, 18, 19, 20

## J_THT_CrossJumper
designator J?, comment #Wert  (value not drawn)
4 Fach Crossjumper
footprint J_THT_CrossJumper (LB-2024-04-19)
pins: 1 C, 2, 3, 4, 5

## J_THT_DB-9
designator J?, comment #Wert
DB-9 Buchse; MF: Wurth Electronics; MP: 618009231121
footprint J_THT_DB9H (LB-2024-04-17)
pins: 1 (io), 2 (io), 3 (io), 4 (io), 5 (io), 6 (io), 7 (io), 8 (io), 9 (io)

## J_THT_DIP24
designator J?, comment DIP24-Socket
footprint DIP-24-W (LB-2025-06-22)
pins: 1, 2, 3, 4, 5, 6, 7, 8, 9, 10, 11, 12, 13, 14, 15, 16, 17, 18, 19, 20, 21, 22, 23, 24

## J_THT_Hohlstecker
designator J?, comment DC-Buchse
footprint J_THT_CJ-25 (LB-2024-04-19)
footprint J_THT_CUI_PJ-006A (LB-2024-12-12)
pins: 1, 2, 3

## J_THT_HPIB
designator J?, comment GPIB-Modul
footprint J_THT_HPIB (LB-24-10-23)
pins: 1, 2, 3, 4, 5, 6, 7, 8, 9, 10, 11, 12, 13, 14, 15, 16, 17, 18, 19, 20, 21, 22, 23, 24, S1 SHIELD

## J_THT_HR911105A
designator J?, comment HR911105A
RJ45-Buchse; MF: hanrun
footprint HR911105A (LB-2024-12-26)
pins: 1 TD+, 2 TD-, 3 RD+, 4 P4, 5 P5, 6 RD-, 8 GND (power), 9 GA, 10 GC, 11 YC, 12 YA, 15 SHIELD, 16 SHIELD

## J_THT_IDC 2x3
designator J?, comment #Wert
Stecker
footprint J_2x3 (LB-2024-04-19)
pins: 1, 2, 3, 4, 5, 6

## J_THT_IDC 2x5
designator J?, comment #Wert
Stecker
footprint J_2x5H IDC (LB-2024-04-19)
footprint J_2x5V IDC (LB-2024-04-19)
footprint J_2x5-V (LB-2024-04-19)
pins: 1, 2, 3, 4, 5, 6, 7, 8, 9, 10

## J_THT_IDC 2x8
designator J?, comment #Wert
Stecker
footprint J_2x8 (LB-2024-04-19)
footprint J_2x8-V (LB-2024-04-19)
pins: 1, 2, 3, 4, 5, 6, 7, 8, 9, 10, 11, 12, 13, 14, 15, 16

## J_THT_IDC 2x10
designator J?, comment #Wert
Stecker
footprint J_2x10 (LB-2024-4-19)
pins: 1, 2, 3, 4, 5, 6, 7, 8, 9, 10, 11, 12, 13, 14, 15, 16, 17, 18, 19, 20

## J_THT_IDC 2x20
designator J?, comment #Wert
IDC-Con 2x20
footprint J_2x20 (LB-2024-4-19)
pins: 1, 2, 3, 4, 5, 6, 7, 8, 9, 10, 11, 12, 13, 14, 15, 16, 17, 18, 19, 20, 21, 22, 23, 24, 25, 26, 27, 28, 29, 30, 31, 32, 33, 34, 35, 36, 37, 38, 39, 40

## J_THT_Printklemme 1x
designator J?, comment #Wert
Printklemme
footprint J_THT_Printklemme 1x (LB-2024-04-17)
pins: 1

## J_THT_Printklemme 2x
designator J?, comment #Wert
Printklemme
footprint J_THT_Printklemme 2x (LB-2024-04-17)
footprint J_THT_PK-S 2x (LB-2024-05-03g)
footprint J_THT_TerminalPlug 2x (LB-2024-04-17)
pins: 1, 2

## J_THT_Printklemme 3x
designator J?, comment #Wert
Printklemme
footprint J_THT_Printklemme 3x (LB-2024-04-17)
footprint J_THT_PK-S 3x (LB-2024-05-03g)
footprint J_THT_TerminalPlug 3X (LB-2024-04-17)
pins: 1, 2, 3 2

## J_THT_Printklemme 4x
designator J?, comment #Wert
Printklemme
footprint J_THT_Printklemme 4x (LB-2024-04-17)
footprint J_THT_TerminalPlug 4X (LB-2024-04-17)
footprint J_Dinkle-ESK635V (LB-2025-06-18)
pins: 1, 2, 3 2, 4 2

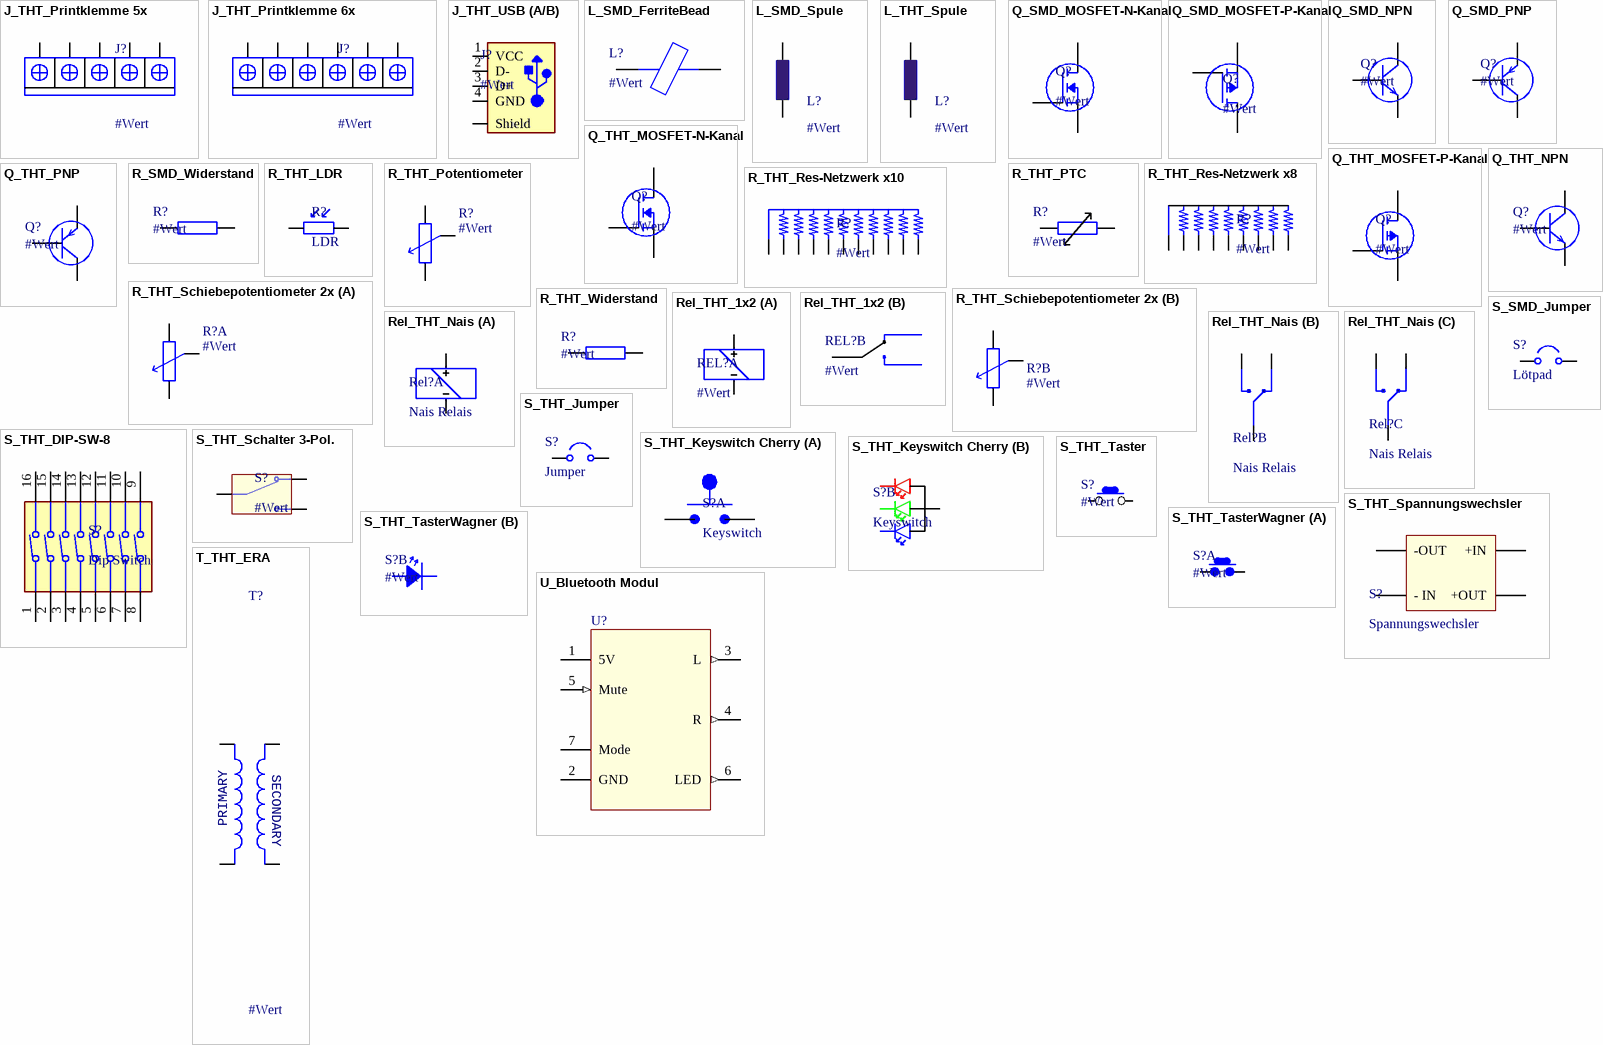
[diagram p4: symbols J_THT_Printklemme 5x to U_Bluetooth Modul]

## J_THT_Printklemme 5x
designator J?, comment #Wert
Stecker
footprint J_THT_Printklemme 5x (LB-2024-04-17)
footprint J_THT_TerminalPlug 5X (LB-2024-04-17)
pins: 1, 2, 3 2, 4 2, 5 2

## J_THT_Printklemme 6x
designator J?, comment #Wert
Printklemme
footprint J_THT_Printklemme 6x (LB-2024-04-17)
footprint J_THT_TerminalPlug 6X (LB-2024-04-17)
pins: 1, 2, 3 2, 4 2, 5 2, 6 2

## J_THT_USB (A/B)
designator J?, comment #Wert
USB Buchse
footprint J_THT_USB-B (LB-2024-04-15)
footprint J_THT_USB-A (LB-2024-04-29)
pins: 1 VCC (power), 2 D- (io), 3 D+ (io), 4 GND (power), SH Shield (power)

## L_SMD_FerriteBead
designator L?, comment #Wert
Ferrit Kern
footprint L_SMD_0805 (LB-2024-04-17)
footprint L_SMD_0603 (LB-2024-04-17)
footprint L_SMD_1206 (LB-2024-04-17)
pins: 1 0, 2 1

## L_SMD_Spule
designator L?, comment #Wert
Spule SMD
footprint L_SMD_NPIS42LS (LB-2024-04-17)
footprint L_SMD_1808C (LB-2024-04-17)
footprint L_SMD_TYA4020 (LB-2024-04-25)
footprint L_SMD_3015 (LB-2024-09-01)
footprint L_SMD_BWVS00606045
pins: 1, 2

## L_THT_Spule
designator L?, comment #Wert
Spule THT
footprint L_THT_5.08 x 8 (LB-2024-04-17)
footprint L_THT_Axial-0.4
pins: 1, 2

## Q_SMD_MOSFET-N-Kanal
designator Q?, comment #Wert
N-Kanal MOSFET; MP: IRFZ44NPBF; MF: Infineon
footprint SOT-23
footprint TO263 (LB-2026-01-02)
pins: 1 G, 2 S, 3 D

## Q_SMD_MOSFET-P-Kanal
designator Q?, comment #Wert
P-Kanal MOSFET; MP: IRFZ44NPBF; MF: Infineon
footprint SOT-23
footprint Q_SOT-223-4 (LB-2025-01-10)
pins: 1 G, 2 S, 3 D

## Q_SMD_NPN
designator Q?, comment #Wert
NPN Transistor
footprint SOT-23
pins: 1 B, 2 E, 3 C

## Q_SMD_PNP
designator Q?, comment #Wert
PNP Transistor
footprint SOT-23
pins: 1 B, 2 E, 3 C

## Q_THT_MOSFET-N-Kanal
designator Q?, comment #Wert
N-Kanal MOSFET; MP: IRFZ44NPBF; MF: Infineon
footprint TO-220-3V (LB-2024-04-17)
pins: 1 G, 2 S, 3 D

## Q_THT_MOSFET-P-Kanal
designator Q?, comment #Wert
P-Kanal MOSFET; MP: IRFZ44NPBF; MF: Infineon
footprint TO-220-3V (LB-2024-04-17)
pins: 1 G, 2 S, 3 D

## Q_THT_NPN
designator Q?, comment #Wert
NPN Transistor
footprint TO3 (LB-2024-04-17)
footprint TO-92-3 (LB-2024-04-17)
footprint TO-220-3H (LB-2024-04-17)
footprint TO-220-3V (LB-2024-04-17)
pins: 1 B, 2 E, 3 C

## Q_THT_PNP
designator Q?, comment #Wert
PNP Transistor
footprint TO-92-3 (LB-2024-04-17)
footprint TO-220-3H (LB-2024-04-17)
footprint TO-220-3V (LB-2024-04-17)
pins: 1 B, 2 E, 3 C

## R_SMD_Widerstand
designator R?, comment #Wert
Widerstand SMD
footprint R_SMD_0603 (LB-2024-04-17)
footprint R_SMD_0805 (LB-2024-04-17)
footprint R_SMD_1206 (LB-2024-04-17)
footprint R_SMD_1808C (LB-2024-04-17)
footprint R_SMD_2010R (LB-2024-04-17)
pins: 1, 2

## R_THT_LDR
designator R?, comment LDR
Light Dependent Resistor
footprint R_THT_LDR (LB-2024-04-18)
pins: 1, 2

## R_THT_Potentiometer
designator R?, comment #Wert
Potentiometer; Set Position: 0.5
footprint R_THT_POT-TP-.2/.4 (LB-2024-04-17)
footprint R_THT_POT-PT15 (LB-2024-04-17)
footprint R_THT_POT-ALPS_V
footprint R_THT_POT-TP-.2/.1 (LB-2024-12-11)
footprint R_THT_Pot-65x75
pins: 1, 2, 3

## R_THT_PTC
designator R?, comment #Wert
Temperatur Widerstand PTC
footprint TO-92-2 (LB-2024-04-18)
pins: 1, 2

## R_THT_Res-Netzwerk x8
designator R?, comment #Wert
Widerstandsnetzwerk 8x
footprint SIP-9
pins: 1, 2, 3, 4, 5, 6, 7, 8, 9

## R_THT_Res-Netzwerk x10
designator R?, comment #Wert
Widerstandsnetzwerk 10x
footprint SIP-11
pins: 1, 2, 3, 4, 5, 6, 7, 8, 9, 10, 11

## R_THT_Schiebepotentiometer 2x
designator R?, comment #Wert
Potentiometer; Set Position: 0.5
footprint R_THT_Shiftpotentiometer (LB-2025-01-23)
part A pins: 1, 2, 6
part B pins: 3, 4, 5 6

## R_THT_Widerstand
designator R?, comment #Wert
Widerstand THT
footprint R_THT_Axial-0.4 (LB-2024-04-17)
footprint R_THT_Axial-0.7 (LB-2024-04-17)
footprint R_THT_Rad
footprint R_THT_0R0 (LB-2024-08-13)
pins: 1, 2

## Rel_THT_1x2
designator REL?, comment #Wert
Relais 1 Öffner, 1 Schließer
footprint Rel_THT_1x 2 (LB-2024-04-18)
footprint Rel_THT_1x 2 - 2 (LB-2024-04-18)
part A pins: 1 +, 2
part B pins: 3, 4 NO, 5

## Rel_THT_Nais
designator Rel?, comment Nais Relais
Nais DS2Y-S-DC12V
footprint Rel_THT_Nais (LB-2024-04-17)
part A pins: 4, 5
part B pins: 1, 2, 3
part C pins: 6, 7, 8

## S_SMD_Jumper
designator S?, comment Lötpad
Lötverbinder
footprint S_SMD_Pad-NC
footprint S_SMD_Pad-NO
pins: 1 0, 2 1

## S_THT_DIP-SW-8
designator S?, comment Dip Switch
Dip Switch 8x
footprint DIP 2x8
pins: 1, 2, 3, 4, 5, 6, 7, 8, 9, 10, 11, 12, 13, 14, 15, 16

## S_THT_Jumper
designator S?, comment Jumper
footprint SIP-2 (LB-2024-04-17)
pins: 1 0, 2 1

## S_THT_Keyswitch Cherry
designator S?, comment Keyswitch
footprint S_THT_KeyswitchCherry (LB-2024-04-18)
part A pins: 1, 2
part B pins: 3, 4, 5, 6

## S_THT_Schalter 3-Pol.
designator S?, comment #Wert
Toggle Switch; MP: 100SP1T1B4M2QE
footprint S_THT_SW-3Pol
pins: 1, 2, 3

## S_THT_Spannungswechsler
designator S?, comment Spannungswechsler
footprint J_2x2 (LB-2024-05-28)
pins: 1 - IN, 2 +OUT, 3 +IN, 4 -OUT

## S_THT_Taster
designator S?, comment #Wert
Taster
footprint S_THT_Taster2kl. (LB-2024-04-17)
footprint S_THT_Taster4gr. (LB-2024-04-17)
footprint S_THT_Taster4kl. (LB-2024-04-17)
footprint S_THT_TasterKomb. (LB-2024-04-17)
pins: 1, 2

## S_THT_TasterWagner
designator S?, comment #Wert
Taster von Professor Herbert Wagner
footprint S_THT_TasterWagner (LB-2024-04-17)
part A pins: 1, 2
part B pins: 3 A, 4 K

## T_THT_ERA
designator T?, comment #Wert
Trafo ERA
footprint T_THT_ERA6V (LB-2024-04-17)
pins: 1 230V, 2 230V, 3 16V, 4 16V

## U_Bluetooth Modul
designator U?, comment Bluetooth-Audio-DIY-Modul  (value not drawn)
Bluetooth Modul
footprint U_BluetoothModul SIP7 (LB-2024-04-19)
pins: 1 5V (power), 2 GND (power), 3 L (out), 4 R (out), 5 Mute (in), 6 LED (out), 7 Mode

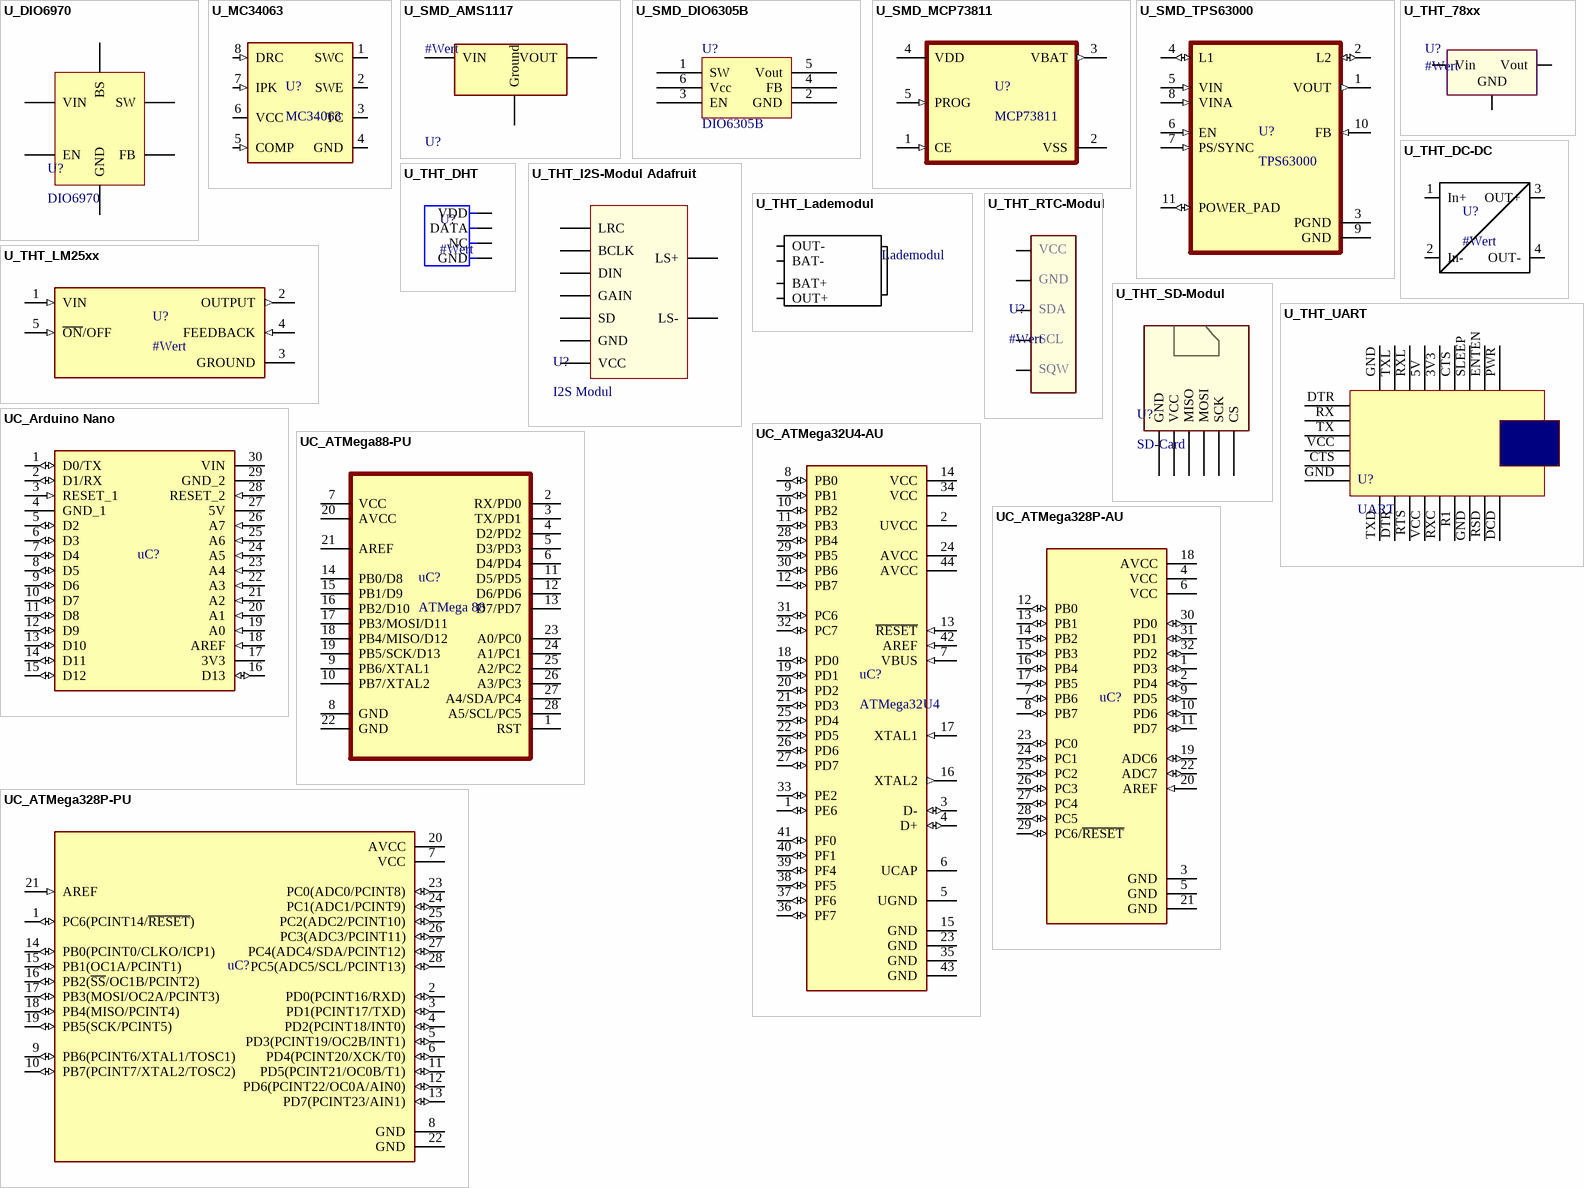
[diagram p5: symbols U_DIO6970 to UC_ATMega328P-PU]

## U_DIO6970
designator U?, comment DIO6970
Buckconverter
footprint SOT23-6 (LB-2024-04-25)
pins: 1 GND, 2 SW, 3 VIN, 4 FB, 5 EN, 6 BS

## U_MC34063
designator U?, comment MC34063
Buck-/Boost-Converter
footprint SO-8 (LB-2024-04-17)
footprint DIP-8 (LB-2024-04-17)
pins: 1 SWC (io), 2 SWE (io), 3 TC, 4 GND (power), 5 COMP (in), 6 VCC (power), 7 IPK (in), 8 DRC (in)

## U_SMD_AMS1117
designator U?, comment #Wert
Linearwandler; Manufacturer Part Number: AMS1117-3.3; Manufacturer: Advanced Monolithic Systems; Dropout Voltage: 1.1V; Output Type: Fixed; Nominal Supply Current: 5mA; Output Current: 1A; Output Voltage: 3.3V; Max Power Dissipation: 1.2W; Max Supply Voltage: 15V; Number Of Outputs: 1; Standoff Height: 0.64mm; Max Junction Temp: +125°C
footprint U_SMD_AMS1117
pins: 1 Ground (power), 2 VOUT, 3 VIN (power)

## U_SMD_DIO6305B
designator U?, comment DIO6305B
Step Up Converter
footprint SOT23-6 (LB-2024-04-25)
pins: 1 SW, 2 GND, 3 EN, 4 FB, 5 Vout, 6 Vcc

## U_SMD_MCP73811
designator U?, comment MCP73811
Charger IC Lithium Ion/Polymer
footprint SOT23-5
pins: 1 CE (in), 2 VSS (power), 3 VBAT (out), 4 VDD (power), 5 PROG (in)

## U_SMD_TPS63000
designator U?, comment TPS63000
Buck-/Boost-Converter
footprint VSON-10 (LB-2024-09-01)
pins: 1 VOUT (out), 2 L2 (io), 3 PGND (power), 4 L1 (io), 5 VIN (in), 6 EN (in), 7 PS/SYNC (in), 8 VINA (in), 9 GND (power), 10 FB (in), 11 POWER_PAD (io)

## U_THT_78xx
designator U?, comment #Wert
Linearwandler
footprint TO-220-3V (LB-2024-04-17)
footprint TO-220-3H (LB-2024-04-17)
pins: 1 Vin, 2 Vout, 3 GND

## U_THT_DC-DC
designator U?, comment #Wert
DC-DC Wandler
footprint U_THT_DCDC (LB-2024-04-17)
pins: 1 In+, 2 In-, 3 OUT+, 4 OUT-

## U_THT_DHT
designator U?, comment #Wert
Temparatur Sensor DHT11/DHT22
footprint U_THT_DHTxx (LB-2024-04-19)
pins: 1 VDD (power), 2 DATA (power), 3 NC, 4 GND (power)

## U_THT_I2S-Modul Adafruit
designator U?, comment I2S Modul
I2S Modul Adafruit
footprint U_THT_I2S-Modul-Adafruit (LB-2024-05-02)
pins: BCLK, DIN, GAIN, GND, LRC, LS+, LS-, SD, VIN VCC

## U_THT_Lademodul
designator U?, comment Lademodul
footprint U_THT_Lademodul (LB-2024-04-25)
pins: 1 OUT-, 2 BAT-, 3 BAT+, 4 OUT+

## U_THT_LM25xx
designator U?, comment #Wert
Spanungswandler Step Up/Down
footprint TO220-5V (LB-2024-0419)
footprint TO220-5H (LB-2024-04-19)
pins: 1 VIN (in), 2 OUTPUT (out), 3 GROUND (power), 4 FEEDBACK (in), 5 ~{ON}/OFF (in)

## U_THT_RTC-Modul
designator U?, comment #Wert
RTC Modul
footprint U_THT_RTC-ModulElegoo (LB-2024-04-19)
pins: 1, 2, 3, 4, 5

## U_THT_SD-Modul
designator U?, comment SD-Card
SD-Modul f. z.B. Arduino o. ESP32
footprint U_THT_SDModulV (LB-2024-04-19)
footprint U_THT_SD-ModulH (LB-2024-04-19)
pins: 1 GND, 2 VCC, 3 MISO, 4 MOSI, 5 SCK, 6 CS

## U_THT_UART
designator U?, comment UART
UART Modul
footprint U_THT_UART-Modul (LB-2024-04-15)
pins: 3V3 13, 5V 12, CTS 14, CTS 19, DCD 8, DTR 1, DTR 23, ENTEN 16, GND 6, GND 9, GND 18, PWR 17, R1 5, RSD 7, RTS 2, RX 22, RXC 4, RXL 11, SLEEP 15, TX 21, TXD 0, TXL 10, VCC 3, VCC 20

## UC_Arduino Nano
designator uC?, comment Arduino Nano  (value not drawn)
Microcontroller
footprint UC_Arduino-Nano (LB-2024-04-18)
pins: 1 D0/TX (io), 2 D1/RX (io), 3 RESET_1 (in), 4 GND_1 (power), 5 D2 (io), 6 D3 (io), 7 D4 (io), 8 D5 (io), 9 D6 (io), 10 D7 (io), 11 D8 (io), 12 D9 (io), 13 D10 (io), 14 D11 (io), 15 D12 (io), 16 D13 (io), 17 3V3 (power), 18 AREF (in), 19 A0 (in), 20 A1 (in), 21 A2 (in), 22 A3 (in), 23 A4 (in), 24 A5 (in), 25 A6 (in), 26 A7 (in), 27 5V (power), 28 RESET_2 (in), 29 GND_2 (power), 30 VIN (power)

## UC_ATMega32U4-AU
designator uC?, comment ATMega32U4
Microcontroller
footprint TQFP-44 (LB-2024-06-15)
pins: 1 PE6 (io), 2 UVCC (power), 3 D- (io), 4 D+ (io), 5 UGND (power), 6 UCAP, 7 VBUS (in), 8 PB0 (io), 9 PB1 (io), 10 PB2 (io), 11 PB3 (io), 12 PB7 (io), 13 ~{RESET} (in), 14 VCC (power), 15 GND (power), 16 XTAL2 (out), 17 XTAL1 (in), 18 PD0 (io), 19 PD1 (io), 20 PD2 (io), 21 PD3 (io), 22 PD5 (io), 23 GND (power), 24 AVCC (power), 25 PD4 (io), 26 PD6 (io), 27 PD7 (io), 28 PB4 (io), 29 PB5 (io), 30 PB6 (io), 31 PC6 (io), 32 PC7 (io), 33 PE2 (io), 34 VCC (power), 35 GND (power), 36 PF7 (io), 37 PF6 (io), 38 PF5 (io), 39 PF4 (io), 40 PF1 (io), 41 PF0 (io), 42 AREF (in), 43 GND (power), 44 AVCC (power)

## UC_ATMega88-PU
designator uC?, comment ATMega 88
Atmel ATMega88-PU; MP: ATMEGA88-20PU
footprint DIP-28 (LB-2024-04-17)
pins: 1 RST, 2 RX/PD0, 3 TX/PD1, 4 D2/PD2, 5 D3/PD3, 6 D4/PD4, 7 VCC, 8 GND, 9 PB6/XTAL1, 10 PB7/XTAL2, 11 D5/PD5, 12 D6/PD6, 13 D7/PD7, 14 PB0/D8, 15 PB1/D9, 16 PB2/D10, 17 PB3/MOSI/D11, 18 PB4/MISO/D12, 19 PB5/SCK/D13, 20 AVCC, 21 AREF, 22 GND, 23 A0/PC0, 24 A1/PC1, 25 A2/PC2, 26 A3/PC3, 27 A4/SDA/PC4, 28 A5/SCL/PC5

## UC_ATMega328P-AU
designator uC?, comment ATMega328(p)-AU  (value not drawn)
Microcontroller
footprint TQFP-32 (LB-2024-04-19)
pins: 1 PD3 (io), 2 PD4 (io), 3 GND (power), 4 VCC (power), 5 GND (power), 6 VCC (power), 7 PB6 (io), 8 PB7 (io), 9 PD5 (io), 10 PD6 (io), 11 PD7 (io), 12 PB0 (io), 13 PB1 (io), 14 PB2 (io), 15 PB3 (io), 16 PB4 (io), 17 PB5 (io), 18 AVCC (power), 19 ADC6 (io), 20 AREF (in), 21 GND (power), 22 ADC7 (io), 23 PC0 (io), 24 PC1 (io), 25 PC2 (io), 26 PC3 (io), 27 PC4 (io), 28 PC5 (io), 29 PC6/~{RESET} (io), 30 PD0 (io), 31 PD1 (io), 32 PD2 (io)

## UC_ATMega328P-PU
designator uC?, comment ATMega328(p)-PU  (value not drawn)
Microcontroller
footprint DIP-28 (LB-2024-04-17)
pins: 1 PC6(PCINT14/~{RESET}) (io), 2 PD0(PCINT16/RXD) (io), 3 PD1(PCINT17/TXD) (io), 4 PD2(PCINT18/INT0) (io), 5 PD3(PCINT19/OC2B/INT1) (io), 6 PD4(PCINT20/XCK/T0) (io), 7 VCC (power), 8 GND (power), 9 PB6(PCINT6/XTAL1/TOSC1) (io), 10 PB7(PCINT7/XTAL2/TOSC2) (io), 11 PD5(PCINT21/OC0B/T1) (io), 12 PD6(PCINT22/OC0A/AIN0) (io), 13 PD7(PCINT23/AIN1) (io), 14 PB0(PCINT0/CLKO/ICP1) (io), 15 PB1(OC1A/PCINT1) (io), 16 PB2(~{SS}/OC1B/PCINT2) (io), 17 PB3(MOSI/OC2A/PCINT3) (io), 18 PB4(MISO/PCINT4) (io), 19 PB5(SCK/PCINT5) (io), 20 AVCC (power), 21 AREF (in), 22 GND (power), 23 PC0(ADC0/PCINT8) (io), 24 PC1(ADC1/PCINT9) (io), 25 PC2(ADC2/PCINT10) (io), 26 PC3(ADC3/PCINT11) (io), 27 PC4(ADC4/SDA/PCINT12) (io), 28 PC5(ADC5/SCL/PCINT13) (io)

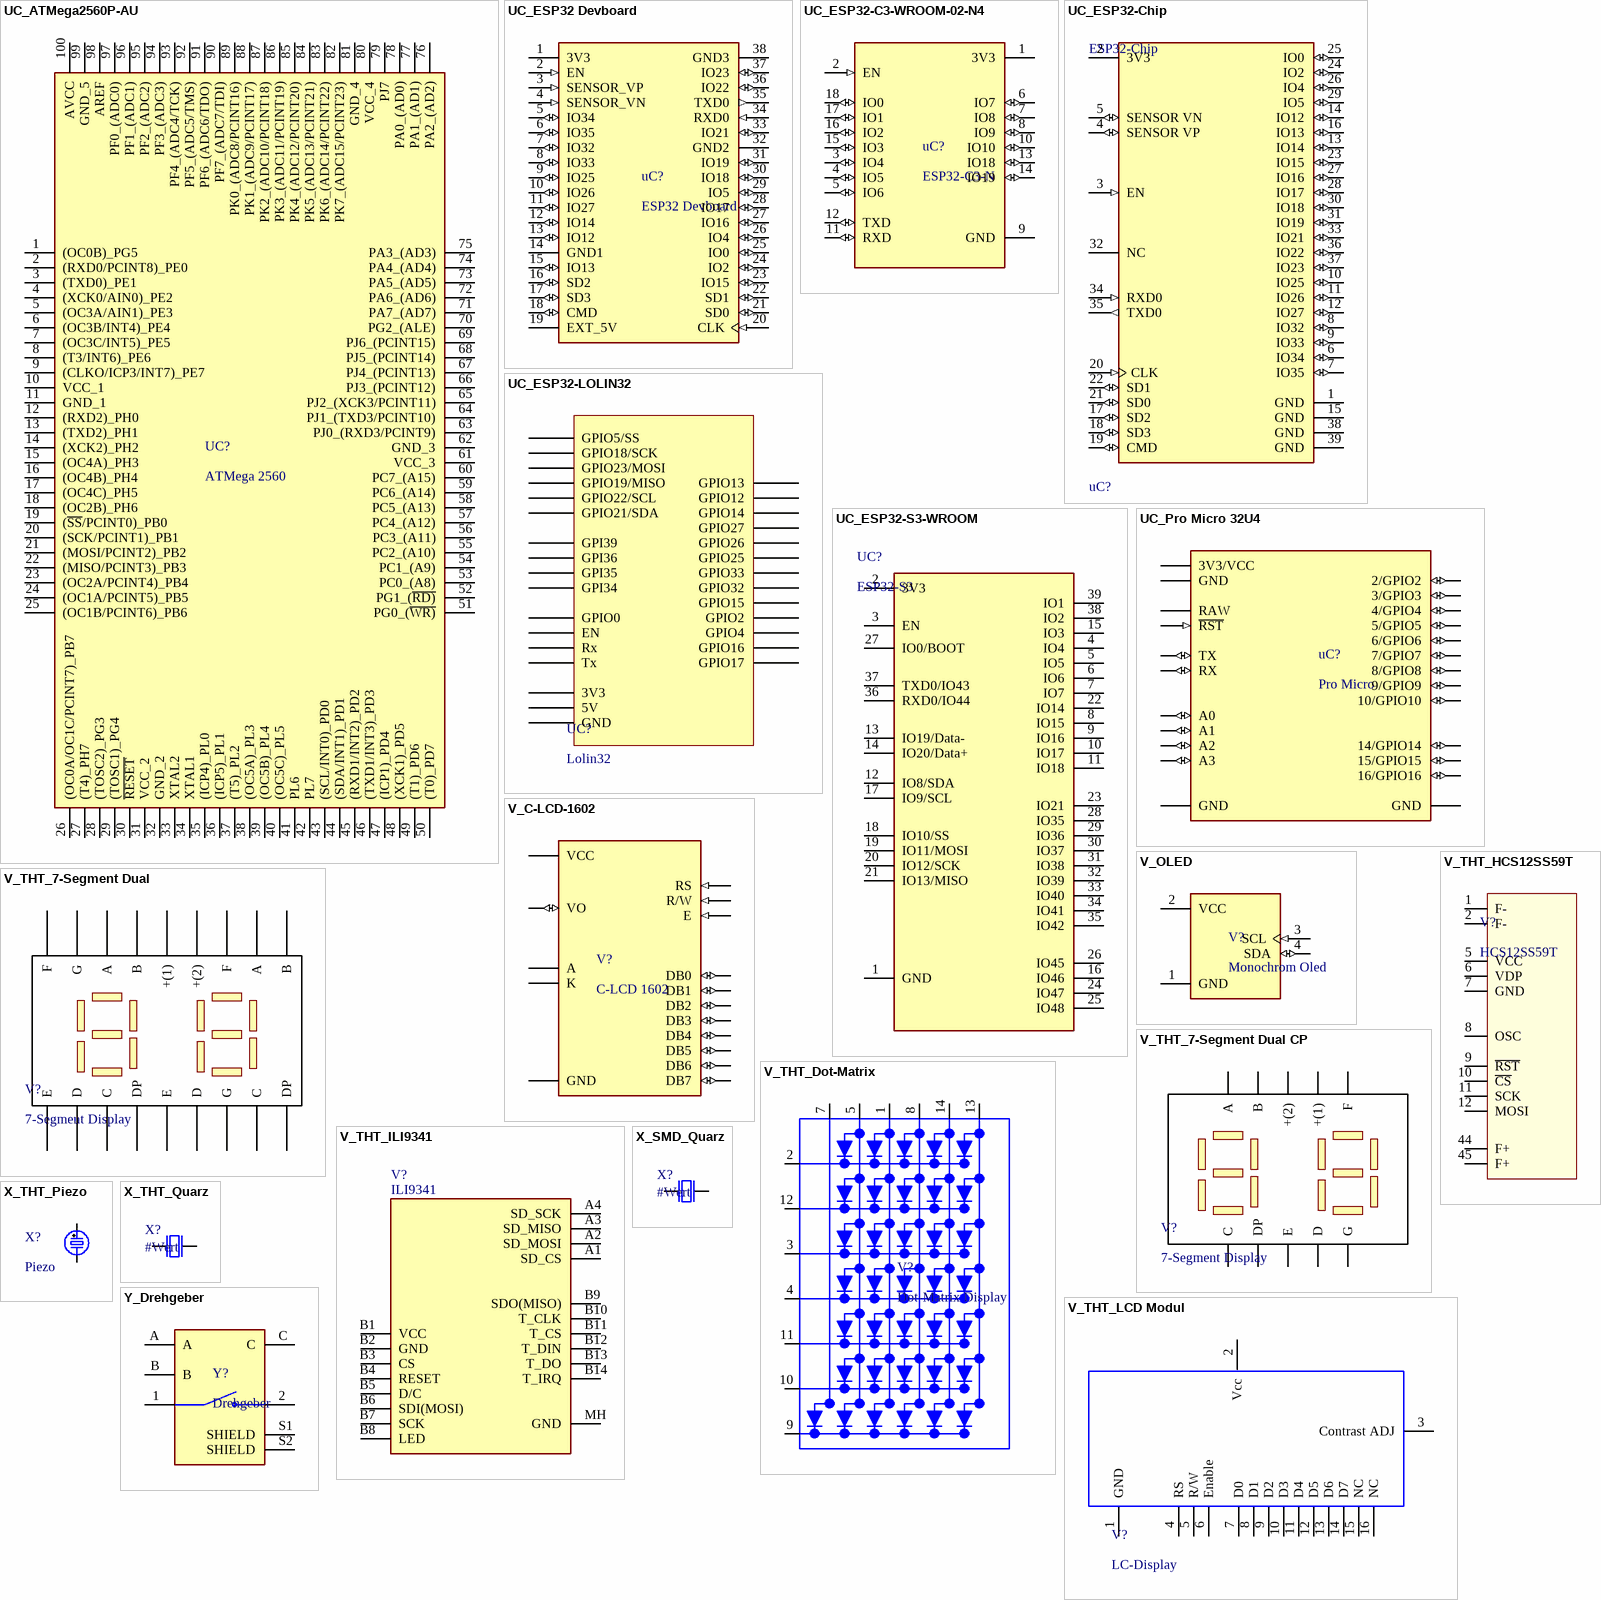
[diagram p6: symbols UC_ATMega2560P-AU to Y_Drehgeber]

## UC_ATMega2560P-AU
designator UC?, comment ATMega 2560
Microcontroller
footprint QFP50P1600X1600X120-100N
pins: 1 (OC0B)_PG5, 2 (RXD0/PCINT8)_PE0, 3 (TXD0)_PE1, 4 (XCK0/AIN0)_PE2, 5 (OC3A/AIN1)_PE3, 6 (OC3B/INT4)_PE4, 7 (OC3C/INT5)_PE5, 8 (T3/INT6)_PE6, 9 (CLKO/ICP3/INT7)_PE7, 10 VCC_1, 11 GND_1, 12 (RXD2)_PH0, 13 (TXD2)_PH1, 14 (XCK2)_PH2, 15 (OC4A)_PH3, 16 (OC4B)_PH4, 17 (OC4C)_PH5, 18 (OC2B)_PH6, 19 (~{SS}/PCINT0)_PB0, 20 (SCK/PCINT1)_PB1, 21 (MOSI/PCINT2)_PB2, 22 (MISO/PCINT3)_PB3, 23 (OC2A/PCINT4)_PB4, 24 (OC1A/PCINT5)_PB5, 25 (OC1B/PCINT6)_PB6, 26 (OC0A/OC1C/PCINT7)_PB7, 27 (T4)_PH7, 28 (TOSC2)_PG3, 29 (TOSC1)_PG4, 30 ~{RESET}, 31 VCC_2, 32 GND_2, 33 XTAL2, 34 XTAL1, 35 (ICP4)_PL0, 36 (ICP5)_PL1, 37 (T5)_PL2, 38 (OC5A)_PL3, 39 (OC5B)_PL4, 40 (OC5C)_PL5, 41 PL6, 42 PL7, 43 (SCL/INT0)_PD0, 44 (SDA/INT1)_PD1, 45 (RXD1/INT2)_PD2, 46 (TXD1/INT3)_PD3, 47 (ICP1)_PD4, 48 (XCK1)_PD5, 49 (T1)_PD6, 50 (T0)_PD7, 51 PG0_(~{WR)}, 52 PG1_(~{RD)}, 53 PC0_(A8), 54 PC1_(A9), 55 PC2_(A10), 56 PC3_(A11), 57 PC4_(A12), 58 PC5_(A13), 59 PC6_(A14), 60 PC7_(A15), 61 VCC_3, 62 GND_3, 63 PJ0_(RXD3/PCINT9), 64 PJ1_(TXD3/PCINT10), 65 PJ2_(XCK3/PCINT11), 66 PJ3_(PCINT12), 67 PJ4_(PCINT13), 68 PJ5_(PCINT14), 69 PJ6_(PCINT15), 70 PG2_(ALE), 71 PA7_(AD7), 72 PA6_(AD6), 73 PA5_(AD5), 74 PA4_(AD4), 75 PA3_(AD3), 76 PA2_(AD2), 77 PA1_(AD1), 78 PA0_(AD0), 79 PJ7, 80 VCC_4, 81 GND_4, 82 PK7_(ADC15/PCINT23), 83 PK6_(ADC14/PCINT22), 84 PK5_(ADC13/PCINT21), 85 PK4_(ADC12/PCINT20), 86 PK3_(ADC11/PCINT19), 87 PK2_(ADC10/PCINT18), 88 PK1_(ADC9/PCINT17), 89 PK0_(ADC8/PCINT16), 90 PF7_(ADC7/TDI), 91 PF6_(ADC6/TDO), 92 PF5_(ADC5/TMS), 93 PF4_(ADC4/TCK), 94 PF3_(ADC3), 95 PF2_(ADC2), 96 PF1_(ADC1), 97 PF0_(ADC0), 98 AREF, 99 GND_5, 100 AVCC

## UC_ESP32 Devboard
designator uC?, comment ESP32 Devboard
ESP32 WROOM Devboard
footprint UC_ESP32-WROOM (LB-2024-04-18)
pins: 1 3V3 (power), 2 EN (in), 3 SENSOR_VP (in), 4 SENSOR_VN (in), 5 IO34 (io), 6 IO35 (io), 7 IO32 (io), 8 IO33 (io), 9 IO25 (io), 10 IO26 (io), 11 IO27 (io), 12 IO14 (io), 13 IO12 (io), 14 GND1 (power), 15 IO13 (io), 16 SD2 (io), 17 SD3 (io), 18 CMD (io), 19 EXT_5V (power), 20 CLK (in), 21 SD0 (io), 22 SD1 (io), 23 IO15 (io), 24 IO2 (io), 25 IO0 (io), 26 IO4 (io), 27 IO16 (io), 28 IO17 (io), 29 IO5 (io), 30 IO18 (io), 31 IO19 (io), 32 GND2 (power), 33 IO21 (io), 34 RXD0 (in), 35 TXD0 (out), 36 IO22 (io), 37 IO23 (io), 38 GND3 (power)

## UC_ESP32-C3-WROOM-02-N4
designator uC?, comment ESP32-C3-N
ESP32-C3
footprint UC_ESP32-C3 (LB-2024-09-01)
pins: 1 3V3 (power), 2 EN (in), 3 IO4 (io), 4 IO5 (io), 5 IO6 (io), 6 IO7 (io), 7 IO8 (io), 8 IO9 (io), 9 GND (power), 10 IO10 (io), 11 RXD (io), 12 TXD (io), 13 IO18 (io), 14 IO19 (io), 15 IO3 (io), 16 IO2 (io), 17 IO1 (io), 18 IO0 (io)

## UC_ESP32-Chip
designator uC?, comment ESP32-Chip
Microcontroller Chip Only
footprint UC_SMD_ESP32 Chip (LB-2024-04-18)
pins: 1 GND (power), 2 3V3 (power), 3 EN (in), 4 SENSOR VP (io), 5 SENSOR VN (io), 6 IO34 (io), 7 IO35 (io), 8 IO32 (io), 9 IO33 (io), 10 IO25 (io), 11 IO26 (io), 12 IO27 (io), 13 IO14 (io), 14 IO12 (io), 15 GND (power), 16 IO13 (io), 17 SD2 (io), 18 SD3 (io), 19 CMD (io), 20 CLK (in), 21 SD0 (io), 22 SD1 (io), 23 IO15 (io), 24 IO2 (io), 25 IO0 (io), 26 IO4 (io), 27 IO16 (io), 28 IO17 (io), 29 IO5 (io), 30 IO18 (io), 31 IO19 (io), 32 NC, 33 IO21 (io), 34 RXD0 (in), 35 TXD0 (out), 36 IO22 (io), 37 IO23 (io), 38 GND (power), 39 GND (power)

## UC_ESP32-LOLIN32
designator UC?, comment Lolin32
ESP32 WMOS LOLIN32
footprint UC_WemosLolin32 (LB-2024-04-20)
pins: 1 3V3, 2 EN, 3 GPI36, 4 GPI39, 5 GPIO32, 6 GPIO33, 7 GPI34, 8 GPI35, 9 GPIO25, 10 GPIO26, 11 GPIO27, 12 GPIO14, 13 GPIO12, 14 GPIO13, 15 5V, 16 GND, 17 Tx, 18 Rx, 19 GPIO22/SCL, 20 GPIO21/SDA, 21 GPIO19/MISO, 22 GPIO23/MOSI, 23 GPIO18/SCK, 24 GPIO5/SS, 25 GPIO17, 26 GPIO16, 27 GPIO4, 28 GPIO0, 29 GPIO2, 30 GPIO15

## UC_ESP32-S3-WROOM
designator UC?, comment ESP32-S3
Mikrocontroller
footprint UC_ESP32S3WROOM (LB-2025-01-10)
pins: 1 GND, 2 3V3, 3 EN, 4 IO4, 5 IO5, 6 IO6, 7 IO7, 8 IO15, 9 IO16, 10 IO17, 11 IO18, 12 IO8/SDA, 13 IO19/Data-, 14 IO20/Data+, 15 IO3, 16 IO46, 17 IO9/SCL, 18 IO10/SS, 19 IO11/MOSI, 20 IO12/SCK, 21 IO13/MISO, 22 IO14, 23 IO21, 24 IO47, 25 IO48, 26 IO45, 27 IO0/BOOT, 28 IO35, 29 IO36, 30 IO37, 31 IO38, 32 IO39, 33 IO40, 34 IO41, 35 IO42, 36 RXD0/IO44, 37 TXD0/IO43, 38 IO2, 39 IO1

## UC_Pro Micro 32U4
designator uC?, comment Pro Micro
ATMega 32U4
footprint UC_Pro Micro 32U4 (LB-2024-04-18)
pins: J3_1 9/GPIO9 (io), J3_2 8/GPIO8 (io), J3_3 7/GPIO7 (io), J3_4 6/GPIO6 (io), J3_5 5/GPIO5 (io), J3_6 4/GPIO4 (io), J3_7 3/GPIO3 (io), J3_8 2/GPIO2 (io), J3_9 GND (power), J3_10 GND (power), J3_11 RX (io), J3_12 TX (io), J4_1 RAW (power), J4_2 GND (power), J4_3 ~{RST} (in), J4_4 3V3/VCC (power), J4_5 A3 (io), J4_6 A2 (io), J4_7 A1 (io), J4_8 A0 (io), J4_9 15/GPIO15 (io), J4_10 14/GPIO14 (io), J4_11 16/GPIO16 (io), J4_12 10/GPIO10 (io)

## V_C-LCD-1602
designator V?, comment C-LCD 1602
LC-Display; MF: Gravitech; MP: LCD-16X2
footprint V_MODULE_LCD-16X2 (LB-2024-11-29)
pins: 1 GND (power), 2 VCC (power), 3 VO (io), 4 RS (in), 5 R/W (in), 6 E (in), 7 DB0 (io), 8 DB1 (io), 9 DB2 (io), 10 DB3 (io), 11 DB4 (io), 12 DB5 (io), 13 DB6 (io), 14 DB7 (io), 15 A (power), 16 K (power)

## V_OLED
designator V?, comment Monochrom Oled
MONOCHROME GRAPHIC OLED DISPLAY MODULE - I2C
footprint V_MODULE_DM-OLED096-636
pins: 1 GND (power), 2 VCC (power), 3 SCL (in), 4 SDA (io)

## V_THT_7-Segment Dual
designator V?, comment 7-Segment Display
7 Segment Display
footprint V_THT_7Segment-Gr. (LB-2024-04-19)
footprint V_THT_7Segement-Kl. (LB-2024-04-19)
pins: 1 E, 2 D, 3 C, 4 DP, 5 E, 6 D, 7 G, 8 C, 9 DP, 10 B, 11 A, 12 F, 13 +(2), 14 +(1), 15 B, 16 A, 17 G, 18 F

## V_THT_7-Segment Dual CP
designator V?, comment 7-Segment Display
7 Segment Display Common Pins
footprint V_THT_7Segment-CP (LB-2024-04-19)
pins: 1 C, 2 DP, 3 E, 4 D, 5 G, 6 F, 7 +(1), 8 +(2), 9 B, 10 A

## V_THT_Dot-Matrix
designator V?, comment Dot-Matrix Display
Dot Matrix Display Module 5 x 7 Common Cathode Row, Common Anode Column Green 2.1V 0.39 L x 0.73 W x 0.14 H (9.80mm x 18.50mm x 3.50mm)
footprint DIP 2x7 (LB-2024-04-19)
pins: 1 ANODE_COLUMN_2, 2 CATHODE_ROW_1, 3 CATHODE_ROW_3, 4 CATHODE_ROW_4, 5 ANODE_COLUMN_1, 7 ANODE_DECIMAL_POINT, 8 ANODE_COLUMN_3, 9 CATHODE_ROW_7, 10 CATHODE_ROW_6, 11 CATHODE_ROW_5, 12 CATHODE_ROW_2, 13 ANODE_COLUMN_5, 14 ANODE_COLUMN_4

## V_THT_HCS12SS59T
designator V?, comment HCS12SS59T
Samsung HCS12SS59T VF DIsplay
footprint V_THT_HCS12SS59T (LB-2026-01-02)
pins: 1 F-, 2 F-, 5 VCC, 6 VDP, 7 GND, 8 OSC, 9 ~{RST}, 10 ~{CS}, 11 SCK, 12 MOSI, 44 F+, 45 F+

## V_THT_ILI9341
designator V?, comment ILI9341
Color 320x240 TFT Touchscreen, ILI9341 Controller Chip
footprint V_THT_ILI9341 (LB-2024-04-19)
pins: A1 SD_CS, A2 SD_MOSI, A3 SD_MISO, A4 SD_SCK, B1 VCC, B2 GND, B3 CS, B4 RESET, B5 D/C, B6 SDI(MOSI), B7 SCK, B8 LED, B9 SDO(MISO), B10 T_CLK, B11 T_CS, B12 T_DIN, B13 T_DO, B14 T_IRQ, MH GND

## V_THT_LCD Modul
designator V?, comment LC-Display
LCD
footprint V_THT_WM-C1610M (LB-2024-04-19)
pins: 1 GND, 2 Vcc, 3 Contrast ADJ, 4 RS, 5 R/W, 6 Enable, 7 D0, 8 D1, 9 D2, 10 D3, 11 D4, 12 D5, 13 D6, 14 D7, 15 NC, 16 NC

## X_SMD_Quarz
designator X?, comment #Wert
Quarz SMD
footprint X_SMD_XTAL (LB-2024-04-17)
pins: 1, 2

## X_THT_Piezo
designator X?, comment Piezo
Piezobuzzer
footprint X_THT_PIEZZO (LB-2024-04-18)
pins: 1, 2

## X_THT_Quarz
designator X?, comment #Wert
Quarz THT
footprint X_THT_XTAL (LB-2024-04-17)
footprint X_THT_ECS327613FLXCTR (LB-2025-06-22)
pins: 1, 2

## Y_Drehgeber
designator Y?, comment Drehgeber
footprint Y_Drehgeber1 (LB-2024-04-19)
pins: 1, 2, A, B, C, S1 SHIELD, S2 SHIELD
